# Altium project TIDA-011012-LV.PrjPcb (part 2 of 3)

## Sheet TIDA-011012-LV Communication.SchDoc
size 431 x 279 mm; Date: Not shown in title block; ApprovedBy: Not shown in title block; CheckedBy: Not shown in title block; Author: Not shown in title block; CompanyName: Not shown in title block; Engineer: Not shown in title block; Organization: Not shown in title block; Address1: Not shown in title block; Address2: Not shown in title block; Address3: Not shown in title block; Address4: Not shown in title block; DocumentNumber: 10; Revision: Use project parameter SCH_Rev; SheetNumber: 10; SheetTotal: 10; PageSetup: Record=PageOptions¦CenterHorizontal=True¦CenterVertical=True¦PrintScale=1.00¦XCorrection=1.00¦YCorrection=1.00¦PrintKind=0¦BorderSize=5000000¦LeftOffset=0¦BottomOffset=0¦Orientation=2¦PaperLength=1000¦PaperWidth=1000¦Scale=100¦PaperSource=15¦PrintQuality=600¦MediaType=1¦DitherType=10¦PaperKind=Letter¦PrintScaleMode=1
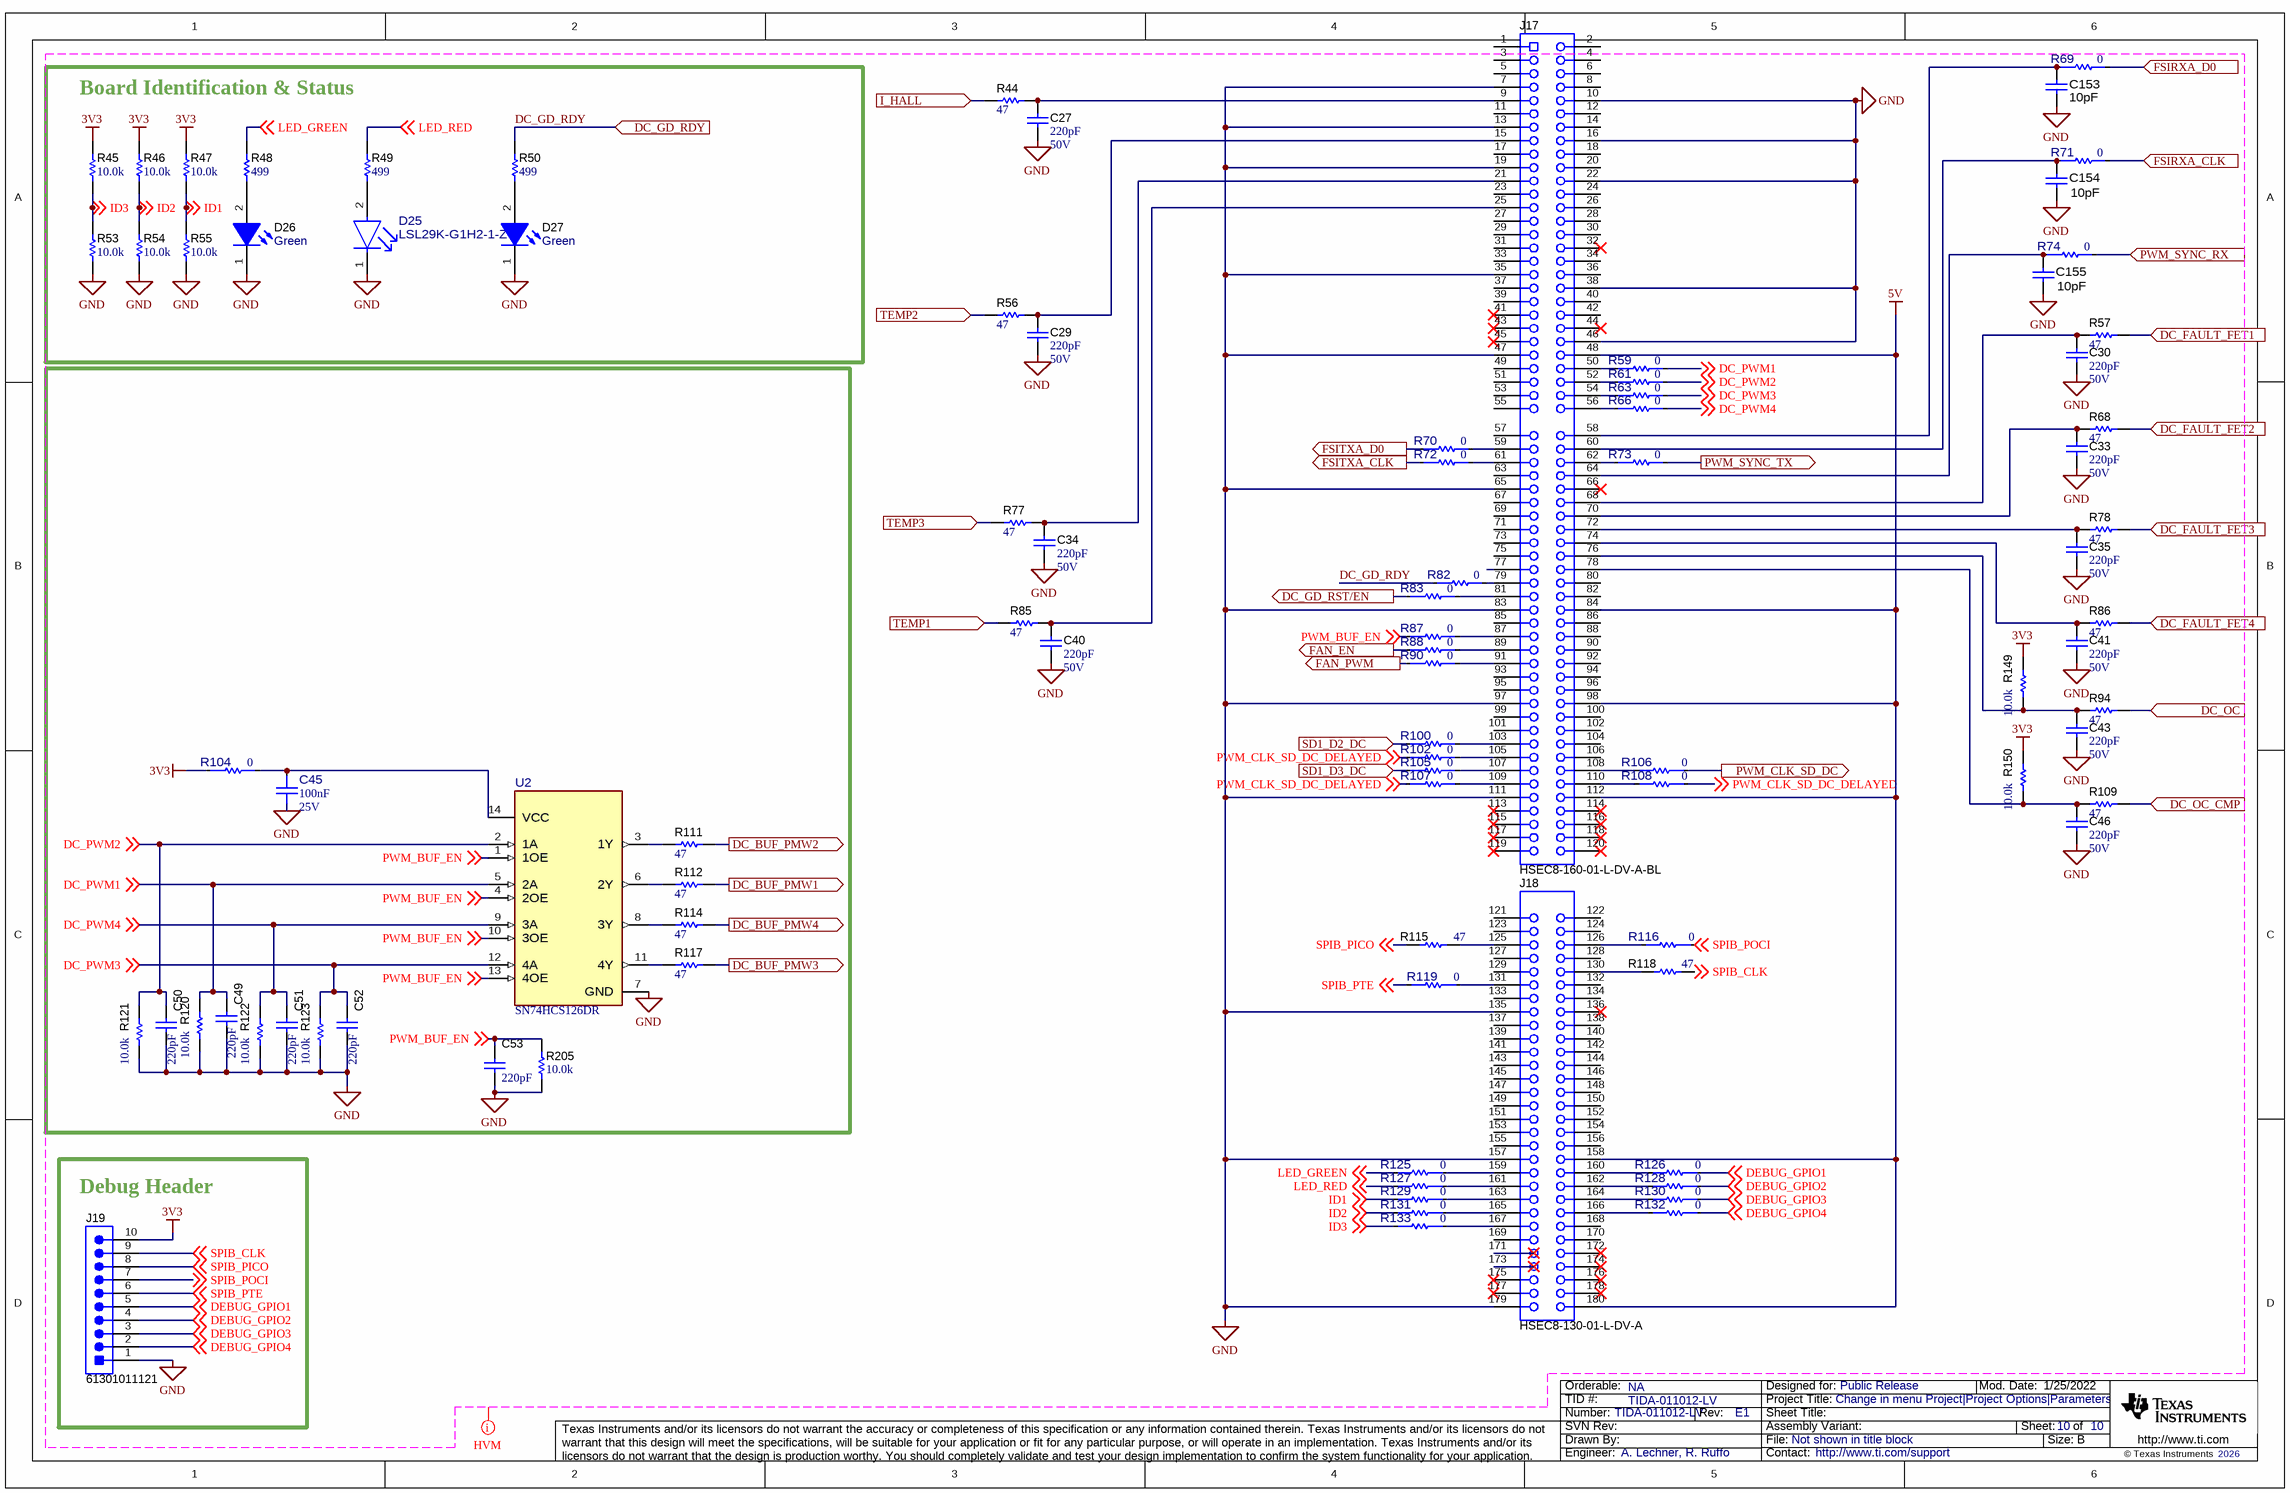
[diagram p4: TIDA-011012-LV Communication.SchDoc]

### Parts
C27  Cap_F: 220pF  VDC_V: 50V  [0603]  (hidden comment: C0603X221K5RACTU)
C29  Cap_F: 220pF  VDC_V: 50V  [0603]  (hidden comment: C0603X221K5RACTU)
C30  Cap_F: 220pF  VDC_V: 50V  [0603]  (hidden comment: C0603X221K5RACTU)
C33  Cap_F: 220pF  VDC_V: 50V  [0603]  (hidden comment: C0603X221K5RACTU)
C34  Cap_F: 220pF  VDC_V: 50V  [0603]  (hidden comment: C0603X221K5RACTU)
C35  Cap_F: 220pF  VDC_V: 50V  [0603]  (hidden comment: C0603X221K5RACTU)
C40  Cap_F: 220pF  VDC_V: 50V  [0603]  (hidden comment: C0603X221K5RACTU)
C41  Cap_F: 220pF  VDC_V: 50V  [0603]  (hidden comment: C0603X221K5RACTU)
C43  Cap_F: 220pF  VDC_V: 50V  [0603]  (hidden comment: C0603X221K5RACTU)
C45  Cap_F: 100nF  VDC_V: 25V  [FP-GMC10X7R104K25NT_0603-MFG]  (hidden comment: GMC10X7R104K25NT)
C46  Cap_F: 220pF  VDC_V: 50V  [0603]  (hidden comment: C0603X221K5RACTU)
C49  Cap_F: 220pF  [0603]  (hidden comment: C0603X221K5RACTU)
C50  Cap_F: 220pF  [0603]  (hidden comment: C0603X221K5RACTU)
C51  Cap_F: 220pF  [0603]  (hidden comment: C0603X221K5RACTU)
C52  Cap_F: 220pF  [0603]  (hidden comment: C0603X221K5RACTU)
C53  Cap_F: 220pF  [0603]  (hidden comment: C0603X221K5RACTU)
C153  Cap_F: 10pF  [0603]  (hidden comment: 0603ZC100KAT2A)
C154  Cap_F: 10pF  [0603]  (hidden comment: 0603ZC100KAT2A)
C155  Cap_F: 10pF  [0603]  (hidden comment: 0603ZC100KAT2A)
D25  LSL29K-G1H2-1-Z  [FP-LSL29K-G1H2-1-Z_0603-0]
D26  value Green  [WL-SMCW_GREEN]  (hidden comment: 150060VS75000)
D27  value Green  [WL-SMCW_GREEN]  (hidden comment: 150060VS75000)
J17  HSEC8-160-01-L-DV-A-BL  [controlCARD-120HSEC]
J18  HSEC8-130-01-L-DV-A  [controlCARD-180HSEC-60pinAddon]
J19  61301011121  [Wurth_61301011121]
R44  ValueDisplayed: 47  [0603]  (hidden comment: ERJ-3GEYJ470V)
R45  ValueDisplayed: 10.0k  [0603]  (hidden comment: ERJ-3EKF1002V)
R46  ValueDisplayed: 10.0k  [0603]  (hidden comment: ERJ-3EKF1002V)
R47  ValueDisplayed: 10.0k  [0603]  (hidden comment: ERJ-3EKF1002V)
R48  ValueDisplayed: 499  [0603]  (hidden comment: CRCW0603499RFKEAC)
R49  ValueDisplayed: 499  [0603]  (hidden comment: CRCW0603499RFKEAC)
R50  ValueDisplayed: 499  [0603]  (hidden comment: CRCW0603499RFKEAC)
R53  ValueDisplayed: 10.0k  [0603]  (hidden comment: ERJ-3EKF1002V)
R54  ValueDisplayed: 10.0k  [0603]  (hidden comment: ERJ-3EKF1002V)
R55  ValueDisplayed: 10.0k  [0603]  (hidden comment: ERJ-3EKF1002V)
R56  ValueDisplayed: 47  [0603]  (hidden comment: ERJ-3GEYJ470V)
R57  ValueDisplayed: 47  [0603]  (hidden comment: ERJ-3GEYJ470V)
R59  value 0  [FP-ERJ-H3G0R00V_0603-MFG]  (hidden comment: ERJ-H3G0R00V)
R61  value 0  [FP-ERJ-H3G0R00V_0603-MFG]  (hidden comment: ERJ-H3G0R00V)
R63  value 0  [FP-ERJ-H3G0R00V_0603-MFG]  (hidden comment: ERJ-H3G0R00V)
R66  value 0  [FP-ERJ-H3G0R00V_0603-MFG]  (hidden comment: ERJ-H3G0R00V)
R68  ValueDisplayed: 47  [0603]  (hidden comment: ERJ-3GEYJ470V)
R69  value 0  [FP-ERJ-H3G0R00V_0603-MFG]  (hidden comment: ERJ-H3G0R00V)
R70  value 0  [FP-ERJ-H3G0R00V_0603-MFG]  (hidden comment: ERJ-H3G0R00V)
R71  value 0  [FP-ERJ-H3G0R00V_0603-MFG]  (hidden comment: ERJ-H3G0R00V)
R72  value 0  [FP-ERJ-H3G0R00V_0603-MFG]  (hidden comment: ERJ-H3G0R00V)
R73  value 0  [FP-ERJ-H3G0R00V_0603-MFG]  (hidden comment: ERJ-H3G0R00V)
R74  value 0  [FP-ERJ-H3G0R00V_0603-MFG]  (hidden comment: ERJ-H3G0R00V)
R77  ValueDisplayed: 47  [0603]  (hidden comment: ERJ-3GEYJ470V)
R78  ValueDisplayed: 47  [0603]  (hidden comment: ERJ-3GEYJ470V)
R82  value 0  [FP-ERJ-H3G0R00V_0603-MFG]  (hidden comment: ERJ-H3G0R00V)
R83  value 0  [FP-ERJ-H3G0R00V_0603-MFG]  (hidden comment: ERJ-H3G0R00V)
R85  ValueDisplayed: 47  [0603]  (hidden comment: ERJ-3GEYJ470V)
R86  ValueDisplayed: 47  [0603]  (hidden comment: ERJ-3GEYJ470V)
R87  value 0  [FP-ERJ-H3G0R00V_0603-MFG]  (hidden comment: ERJ-H3G0R00V)
R88  value 0  [FP-ERJ-H3G0R00V_0603-MFG]  (hidden comment: ERJ-H3G0R00V)
R90  value 0  [FP-ERJ-H3G0R00V_0603-MFG]  (hidden comment: ERJ-H3G0R00V)
R94  ValueDisplayed: 47  [0603]  (hidden comment: ERJ-3GEYJ470V)
R100  value 0  [FP-ERJ-H3G0R00V_0603-MFG]  (hidden comment: ERJ-H3G0R00V)
R102  value 0  [FP-ERJ-H3G0R00V_0603-MFG]  (hidden comment: ERJ-H3G0R00V)
R104  value 0  [FP-ERJ-H3G0R00V_0603-MFG]  (hidden comment: ERJ-H3G0R00V)
R105  value 0  [FP-ERJ-H3G0R00V_0603-MFG]  (hidden comment: ERJ-H3G0R00V)
R106  value 0  [FP-ERJ-H3G0R00V_0603-MFG]  (hidden comment: ERJ-H3G0R00V)
R107  value 0  [FP-ERJ-H3G0R00V_0603-MFG]  (hidden comment: ERJ-H3G0R00V)
R108  value 0  [FP-ERJ-H3G0R00V_0603-MFG]  (hidden comment: ERJ-H3G0R00V)
R109  ValueDisplayed: 47  [0603]  (hidden comment: ERJ-3GEYJ470V)
R111  ValueDisplayed: 47  [0603]  (hidden comment: ERJ-3GEYJ470V)
R112  ValueDisplayed: 47  [0603]  (hidden comment: ERJ-3GEYJ470V)
R114  ValueDisplayed: 47  [0603]  (hidden comment: ERJ-3GEYJ470V)
R115  ValueDisplayed: 47  [0603]  (hidden comment: ERJ-3GEYJ470V)
R116  value 0  [FP-ERJ-H3G0R00V_0603-MFG]  (hidden comment: ERJ-H3G0R00V)
R117  ValueDisplayed: 47  [0603]  (hidden comment: ERJ-3GEYJ470V)
R118  ValueDisplayed: 47  [0603]  (hidden comment: ERJ-3GEYJ470V)
R119  value 0  [FP-ERJ-H3G0R00V_0603-IPC_B]  (hidden comment: ERJ-H3G0R00V)
R120  ValueDisplayed: 10.0k  [0603]  (hidden comment: ERJ-3EKF1002V)
R121  ValueDisplayed: 10.0k  [0603]  (hidden comment: ERJ-3EKF1002V)
R122  ValueDisplayed: 10.0k  [0603]  (hidden comment: ERJ-3EKF1002V)
R123  ValueDisplayed: 10.0k  [0603]  (hidden comment: ERJ-3EKF1002V)
R125  value 0  [FP-ERJ-H3G0R00V_0603-MFG]  (hidden comment: ERJ-H3G0R00V)
R126  value 0  [FP-ERJ-H3G0R00V_0603-MFG]  (hidden comment: ERJ-H3G0R00V)
R127  value 0  [FP-ERJ-H3G0R00V_0603-MFG]  (hidden comment: ERJ-H3G0R00V)
R128  value 0  [FP-ERJ-H3G0R00V_0603-MFG]  (hidden comment: ERJ-H3G0R00V)
R129  value 0  [FP-ERJ-H3G0R00V_0603-MFG]  (hidden comment: ERJ-H3G0R00V)
R130  value 0  [FP-ERJ-H3G0R00V_0603-MFG]  (hidden comment: ERJ-H3G0R00V)
R131  value 0  [FP-ERJ-H3G0R00V_0603-MFG]  (hidden comment: ERJ-H3G0R00V)
R132  value 0  [FP-ERJ-H3G0R00V_0603-MFG]  (hidden comment: ERJ-H3G0R00V)
R133  value 0  [FP-ERJ-H3G0R00V_0603-MFG]  (hidden comment: ERJ-H3G0R00V)
R149  ValueDisplayed: 10.0k  [0603]  (hidden comment: ERJ-3EKF1002V)
R150  ValueDisplayed: 10.0k  [0603]  (hidden comment: ERJ-3EKF1002V)
R205  ValueDisplayed: 10.0k  [0603]  (hidden comment: ERJ-3EKF1002V)
U2  SN74HCS126DR  [D0014A-MFG]

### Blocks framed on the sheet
Board Identification & Status: D25-D27 R45-R50 R53-R55
Debug Header: J19

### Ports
DC_BUF_PMW1 (out), DC_BUF_PMW2 (out), DC_BUF_PMW3 (out), DC_BUF_PMW4 (out), DC_FAULT_FET1 (in), DC_FAULT_FET2 (in), DC_FAULT_FET3 (in), DC_FAULT_FET4 (in), DC_GD_RDY (in), DC_GD_RST/EN (out), DC_OC (in), DC_OC_CMP (in), FAN_EN (out), FAN_PWM (out), FSIRXA_CLK (in), FSIRXA_D0 (in), FSITXA_CLK (out), FSITXA_D0 (out), I_HALL (in), PWM_CLK_SD_DC (out), PWM_SYNC_RX (in), PWM_SYNC_TX (out), SD1_D2_DC (in), SD1_D3_DC (in), TEMP1 (in), TEMP2 (in), TEMP3 (in)

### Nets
3V3: J19.10 R45.2 R46.2 R47.2 R104.1 R149.2 R150.2
5V: J17.48 J17.84 J17.98 J17.112 J18.158 J18.180
GND: C27.2 C29.2 C30.2 C33.2 C34.2 C35.2 C40.2 C41.2 C43.2 C45.1 C46.2 C49.1 C50.1 C51.1 C52.1 C53.1 C153.2 C154.2 C155.2 D25.1(CATHODE) D26.1(K) D27.1(K) J17.7 J17.10 J17.13 J17.16 J17.19 J17.22 J17.35 J17.38 J17.46 J17.47 J17.65 J17.83 J17.97 J17.111 J18.135 J18.157 J18.179 J19.1 R53.1 R54.1 R55.1 R120.1 R121.1 R122.1 R123.1 R205.1 U2.7(GND)
CLK_MOD_DC: R106.1 ; port PWM_CLK_SD_DC
DATA_I_DC: R100.1 ; port SD1_D2_DC
DATA_V_DC: R105.1 ; port SD1_D3_DC
DC_BUF_PMW1: R112.2 ; port DC_BUF_PMW1
DC_BUF_PMW2: R111.2 ; port DC_BUF_PMW2
DC_BUF_PMW3: R117.2 ; port DC_BUF_PMW3
DC_BUF_PMW4: R114.2 ; port DC_BUF_PMW4
DC_FAULT_FET1: R57.2 ; port DC_FAULT_FET1
DC_FAULT_FET2: R68.2 ; port DC_FAULT_FET2
DC_FAULT_FET3: R78.2 ; port DC_FAULT_FET3
DC_FAULT_FET4: R86.2 ; port DC_FAULT_FET4
DC_GD_RDY: R50.2 R82.1 ; port DC_GD_RDY
DC_GD_RST/EN: R83.1 ; port DC_GD_RST/EN
DC_OC: R94.2 ; port DC_OC
DC_OC_CMP: R109.2 ; port DC_OC_CMP
DC_PWM1: C49.2 R59.2 R120.2 U2.5(2A) ; off-sheet DC_PWM1
DC_PWM2: C50.2 R61.2 R121.2 U2.2(1A) ; off-sheet DC_PWM2
DC_PWM3: C52.2 R63.2 R123.2 U2.12(4A) ; off-sheet DC_PWM3
DC_PWM4: C51.2 R66.2 R122.2 U2.9(3A) ; off-sheet DC_PWM4
DEBUG_GPIO1: J19.5 R126.1 ; off-sheet DEBUG_GPIO1
DEBUG_GPIO2: J19.4 R128.1 ; off-sheet DEBUG_GPIO2
DEBUG_GPIO3: J19.3 R130.1 ; off-sheet DEBUG_GPIO3
DEBUG_GPIO4: J19.2 R132.1 ; off-sheet DEBUG_GPIO4
FAN_EN: R88.1 ; port FAN_EN
FAN_PWM: R90.1 ; port FAN_PWM
FSIRXA_CLK: R71.2 ; port FSIRXA_CLK
FSIRXA_D0: R69.2 ; port FSIRXA_D0
FSITXA_CLK: R72.1 ; port FSITXA_CLK
FSITXA_D0: R70.1 ; port FSITXA_D0
I_HALL: R44.1 ; port I_HALL
ID1: R47.1 R55.2 R129.2 ; off-sheet ID1
ID2: R46.1 R54.2 R131.2 ; off-sheet ID2
ID3: R45.1 R53.2 R133.2 ; off-sheet ID3
LED_GREEN: R48.2 R125.2 ; off-sheet LED_GREEN
LED_RED: R49.2 R127.2 ; off-sheet LED_RED
PWM_BUF_EN: C53.2 R87.1 R205.2 U2.1(1OE) U2.4(2OE) U2.10(3OE) U2.13(4OE) ; off-sheet PWM_BUF_EN
PWM_CLK_SD_DC_DELAYED: R102.1 R107.1 R108.1 ; off-sheet PWM_CLK_SD_DC_DELAYED
PWM_SYNC_RX: R74.2 ; port PWM_SYNC_RX
PWM_SYNC_TX: R73.2 ; port PWM_SYNC_TX
SPIB_CLK: J19.9 R118.2 ; off-sheet SPIB_CLK
SPIB_PICO: J19.8 R115.1 ; off-sheet SPIB_PICO
SPIB_POCI: J19.7 R116.1 ; off-sheet SPIB_POCI
SPIB_PTE: J19.6 R119.2 ; off-sheet SPIB_PTE
TEMP1: R85.1 ; port TEMP1
TEMP2: R56.1 ; port TEMP2
TEMP3: R77.1 ; port TEMP3
NetC27_1: C27.1 J17.9 R44.2
NetC29_1: C29.1 J17.15 R56.2
NetC30_1: C30.1 J17.68 R57.1
NetC33_1: C33.1 J17.70 R68.1
NetC34_1: C34.1 J17.21 R77.2
NetC35_1: C35.1 J17.72 R78.1
NetC40_1: C40.1 J17.25 R85.2
NetC41_1: C41.1 J17.74 R86.1
NetC43_1: C43.1 J17.76 R94.1 R149.1
NetC45_2: C45.2 R104.2 U2.14(VCC)
NetC46_1: C46.1 J17.78 R109.1 R150.1
NetC153_1: C153.1 J17.58 R69.1
NetC154_1: C154.1 J17.60 R71.1
NetC155_1: C155.1 J17.64 R74.1
NetD25_2: D25.2(ANODE) R49.1
NetD26_2: D26.2(A) R48.1
NetD27_2: D27.2(A) R50.1
NetJ17_50: J17.50 R59.1
NetJ17_52: J17.52 R61.1
NetJ17_54: J17.54 R63.1
NetJ17_56: J17.56 R66.1
NetJ17_59: J17.59 R70.2
NetJ17_61: J17.61 R72.2
NetJ17_62: J17.62 R73.1
NetJ17_79: J17.79 R82.2
NetJ17_81: J17.81 R83.2
NetJ17_87: J17.87 R87.2
NetJ17_89: J17.89 R88.2
NetJ17_91: J17.91 R90.2
NetJ17_103: J17.103 R100.2
NetJ17_105: J17.105 R102.2
NetJ17_107: J17.107 R105.2
NetJ17_108: J17.108 R106.2
NetJ17_109: J17.109 R107.2
NetJ17_110: J17.110 R108.2
NetJ18_125: J18.125 R115.2
NetJ18_126: J18.126 R116.2
NetJ18_130: J18.130 R118.1
NetJ18_131: J18.131 R119.1
NetJ18_159: J18.159 R125.1
NetJ18_160: J18.160 R126.2
NetJ18_161: J18.161 R127.1
NetJ18_162: J18.162 R128.2
NetJ18_163: J18.163 R129.1
NetJ18_164: J18.164 R130.2
NetJ18_165: J18.165 R131.1
NetJ18_166: J18.166 R132.2
NetJ18_167: J18.167 R133.1
NetR111_1: R111.1 U2.3(1Y)
NetR112_1: R112.1 U2.6(2Y)
NetR114_1: R114.1 U2.8(3Y)
NetR117_1: R117.1 U2.11(4Y)

Not connected (* = marked no-connect by the designer): J17 1 2 3 4 5 6 8 11 12 14 17 18 20 23 24 26 27 28 29 30 31 32* 33 34 36 37 39 40 41* 42 43* 44* 45* 49 51 53 55 57 63 66* 67 69 71 73 75 77 80 82 85 86 88 90 92 93 94 95 96 99 100 101 102 104 106 113* 114* 115* 116* 117* 118* 119* 120*; J18 121 122 123 124 127 128 129 132 133 134 136* 137 138 139 140 141 142 143 144 145 146 147 148 149 150 151 152 153 154 155 156 168 169 170 171* 172* 173* 174* 175* 176* 177* 178*

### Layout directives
net class HVM: 3V3, 5V, DC_GD_RDY, DC_PWM1, DC_PWM2, DC_PWM3, DC_PWM4, DEBUG_GPIO1, DEBUG_GPIO2, DEBUG_GPIO3, DEBUG_GPIO4, GND, ID1, ID2, ID3, LED_GREEN, LED_RED, PWM_BUF_EN, PWM_CLK_SD_DC_DELAYED, SPIB_CLK, SPIB_PICO, SPIB_POCI, SPIB_PTE

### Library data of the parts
C27 C29 C30 C33-C35 C40 C41 C43 C46 = CMP-0006982-4: CAP, CERM, 220 pF, 50 V, +/- 10%, X7R, 0603; Manufacturer: Kemet; TaMin_C: -55°C; Polarized: N; SizeAreaWB_mm2: 4.68; Value1: Unknown; U/M: EA; Value: 220pF; TaMax_C: 125°C; SizeZ_mm: 1; SizeX_mm: 1.6; SizeY_mm: 0.8; SizeArea_mm2: 1.28; AEC Category: Q200
C45 = CMP-0094950-1: 0.1 µF ±10% 25V Ceramic Capacitor X7R 0603 (1608 Metric); Manufacturer: CAL-CHIP ELECTRONICS; AEC Qualified: No; SizeZ_mm: 1mm; Value: 100nF; ValueDisplayed: 0.1uF; TempCo: 30ppm/°C
C49-C53 = CMP-0006982-4: CAP, CERM, 220 pF, 50 V, +/- 10%, X7R, 0603; Manufacturer: Kemet; TaMin_C: -55°C; Polarized: N; SizeAreaWB_mm2: 4.68; Value1: Unknown; U/M: EA; Value: 220pF; TaMax_C: 125°C; SizeZ_mm: 1; SizeX_mm: 1.6; SizeY_mm: 0.8; Value2: 50V; SizeArea_mm2: 1.28; AEC Category: Q200
C153-C155 = CMP-0006811-4: CAP, CERM, 10 pF, 10 V, +/- 10%, X7R, 0603; Manufacturer: AVX; TaMin_C: -55°C; Polarized: N; SizeAreaWB_mm2: 4.68; Value1: Unknown; U/M: EA; Value: 10pF; TaMax_C: 125°C; SizeZ_mm: 1; SizeX_mm: 1.6; SizeY_mm: 0.8; Value2: 10V; SizeArea_mm2: 1.28; AEC Category: Q200
D25 = CMP-0092845-1: LED Uni-Color Red 643nm 2-Pin Chip 0603(1608Metric) T/R; Manufacturer: OSRAM Opto Semiconductors; AEC Grade: Grade 2; LuminousFlux_PhiV: 8.1/16.1lm; Vf_V: 1.8V; Forward Current: 2mA; Led Orientation: Top View; SizeZ_mm: 0.67mm; AEC Qualified: Yes; Luminous Intensity: 1.8-2.24/3.55-4.5mcd; Vr_V: 12V; Angle: 160°; LambdaD: 630nm; Tjmax_C: 110°C
D26 D27 = CMP-0002894-2: LED, Green, SMD; Manufacturer: Wurth Elektronik; Type: AlInGaP; Value2: 2V; Io_A: 20mA; Value1: W
J17 = CMP-0003814-2: C2000 controlCARD-120HSEC connector, SMT; Manufacturer: Samtec; Note: The pin numbering does not match Samtec datasheet
J18 = CMP-0003859-2: C2000 controlCARD-180HSEC (60-pin addon) connector, SMT; Manufacturer: Samtec; Note: The pin numbering does not match Samtec datasheet
J19 = CMP-0054804-1: Header, 2.54mm, 10x1, Gold, TH; Manufacturer: Wurth Elektronik; CNHeader: TRUE; Shrouded: N; Gender: Male; Row_Count: 1; Pitch_mm: 2.54; CT: FALSE
R44 R56 R57 R68 R77 R78 R85 R86 R94 R109 R111 R112 R114 R115 R117 R118 = CMP-0025880-3: RES, 47, 5%, 0.1 W, AEC-Q200 Grade 0, 0603; Manufacturer: Panasonic; Power_W: 100mW; TempCo: 200 ppm/C; Value_Code: 47R0; U/M: EA; Value: 47; EIA_Code: E24; SizeX_mm: 1.6; SizeY_mm: 0.8; SizeZ_mm: 1; Value2: 0.1W; SizeArea_mm2: 1.28; AEC Qualified: Y; AEC Grade: 0; AEC Category: Q200
R45-R47 R53-R55 R120-R123 R149 R150 R205 = CMP-0022684-3: RES, 10.0 k, 1%, 0.1 W, 0603; Manufacturer: Panasonic; Power_W: 100mW; TempCo: 100 ppm/C; Value_Code: 10k0; U/M: EA; Value: 10.0k; EIA_Code: E96; Res_ohm: 10k; SizeX_mm: 1.6; SizeY_mm: 0.8; SizeZ_mm: 1; Value2: 0.1W; SizeArea_mm2: 1.28; VDC_V: 75V; AEC Category: Q200
R48-R50 = CMP-0082532-1: RES, 499, 1%, 0.1 W, 0603; Manufacturer: Vishay-Dale; Power_W: 100mW; TempCo: 100 ppm/C; SizeAreaWB_mm2: 4.68; Value_Code: 499R; Value: 499; EIA_Code: E96; SizeX_mm: 1.6; SizeY_mm: 0.8; SizeZ_mm: 1; Value2: 0.1W; SizeArea_mm2: 1.28; AEC Qualified: N; VDC_V: 75V; AEC Category: Q200
R59 R61 R63 R66 R69-R74 R82 R83 R87 R88 R90 R100 R102 R104-R108 R116 R119 R125-R133 = CMP-0097467-1: 0 Ohms Jumper 0.125W, 1/8W Chip Resistor 0603 (1608 Metric) Automotive AEC-Q200 Thick Film; Manufacturer: Panasonic; VDC_V: 75V; Power_W: 125mW; AEC Qualified: Yes; SizeZ_mm: 0.55mm; AEC Grade: Grade 0
U2 = CMP-0093039-1: Schmitt-trigger inputs quadruple bus buffer gates with 3-state outputs 14-SOIC -40 to 125; Manufacturer: Texas Instruments; Min Supply Voltage: 2V; TJmax_C: +150°C; Logic Function Desc: Non-Inverting; Number Of Inputs: 1; AEC Qualified: No; Max Supply Voltage: 6V; SizeZ_mm: 1.75mm; PositionCount: 4; TaMin_C: -40°C; Standoff Height: 0.1mm; Nominal Supply Current: 0.1uA; TaMax_C: +125°C; Propagation Delay: 7ns

## Sheet TIDA-011012-LV DC IV Sensing.SchDoc
size 431 x 279 mm; Date: Not shown in title block; ApprovedBy: Not shown in title block; CheckedBy: Not shown in title block; Author: Not shown in title block; CompanyName: Not shown in title block; Engineer: Not shown in title block; Organization: Not shown in title block; Address1: Not shown in title block; Address2: Not shown in title block; Address3: Not shown in title block; Address4: Not shown in title block; DocumentNumber: 5; Revision: Use project parameter SCH_Rev; SheetNumber: 5; SheetTotal: 10; PageSetup: Record=PageOptions¦CenterHorizontal=True¦CenterVertical=True¦PrintScale=1.00¦XCorrection=1.00¦YCorrection=1.00¦PrintKind=0¦BorderSize=5000000¦LeftOffset=0¦BottomOffset=0¦Orientation=2¦PaperLength=1000¦PaperWidth=1000¦Scale=100¦PaperSource=15¦PrintQuality=600¦MediaType=1¦DitherType=10¦PaperKind=Letter¦PrintScaleMode=1
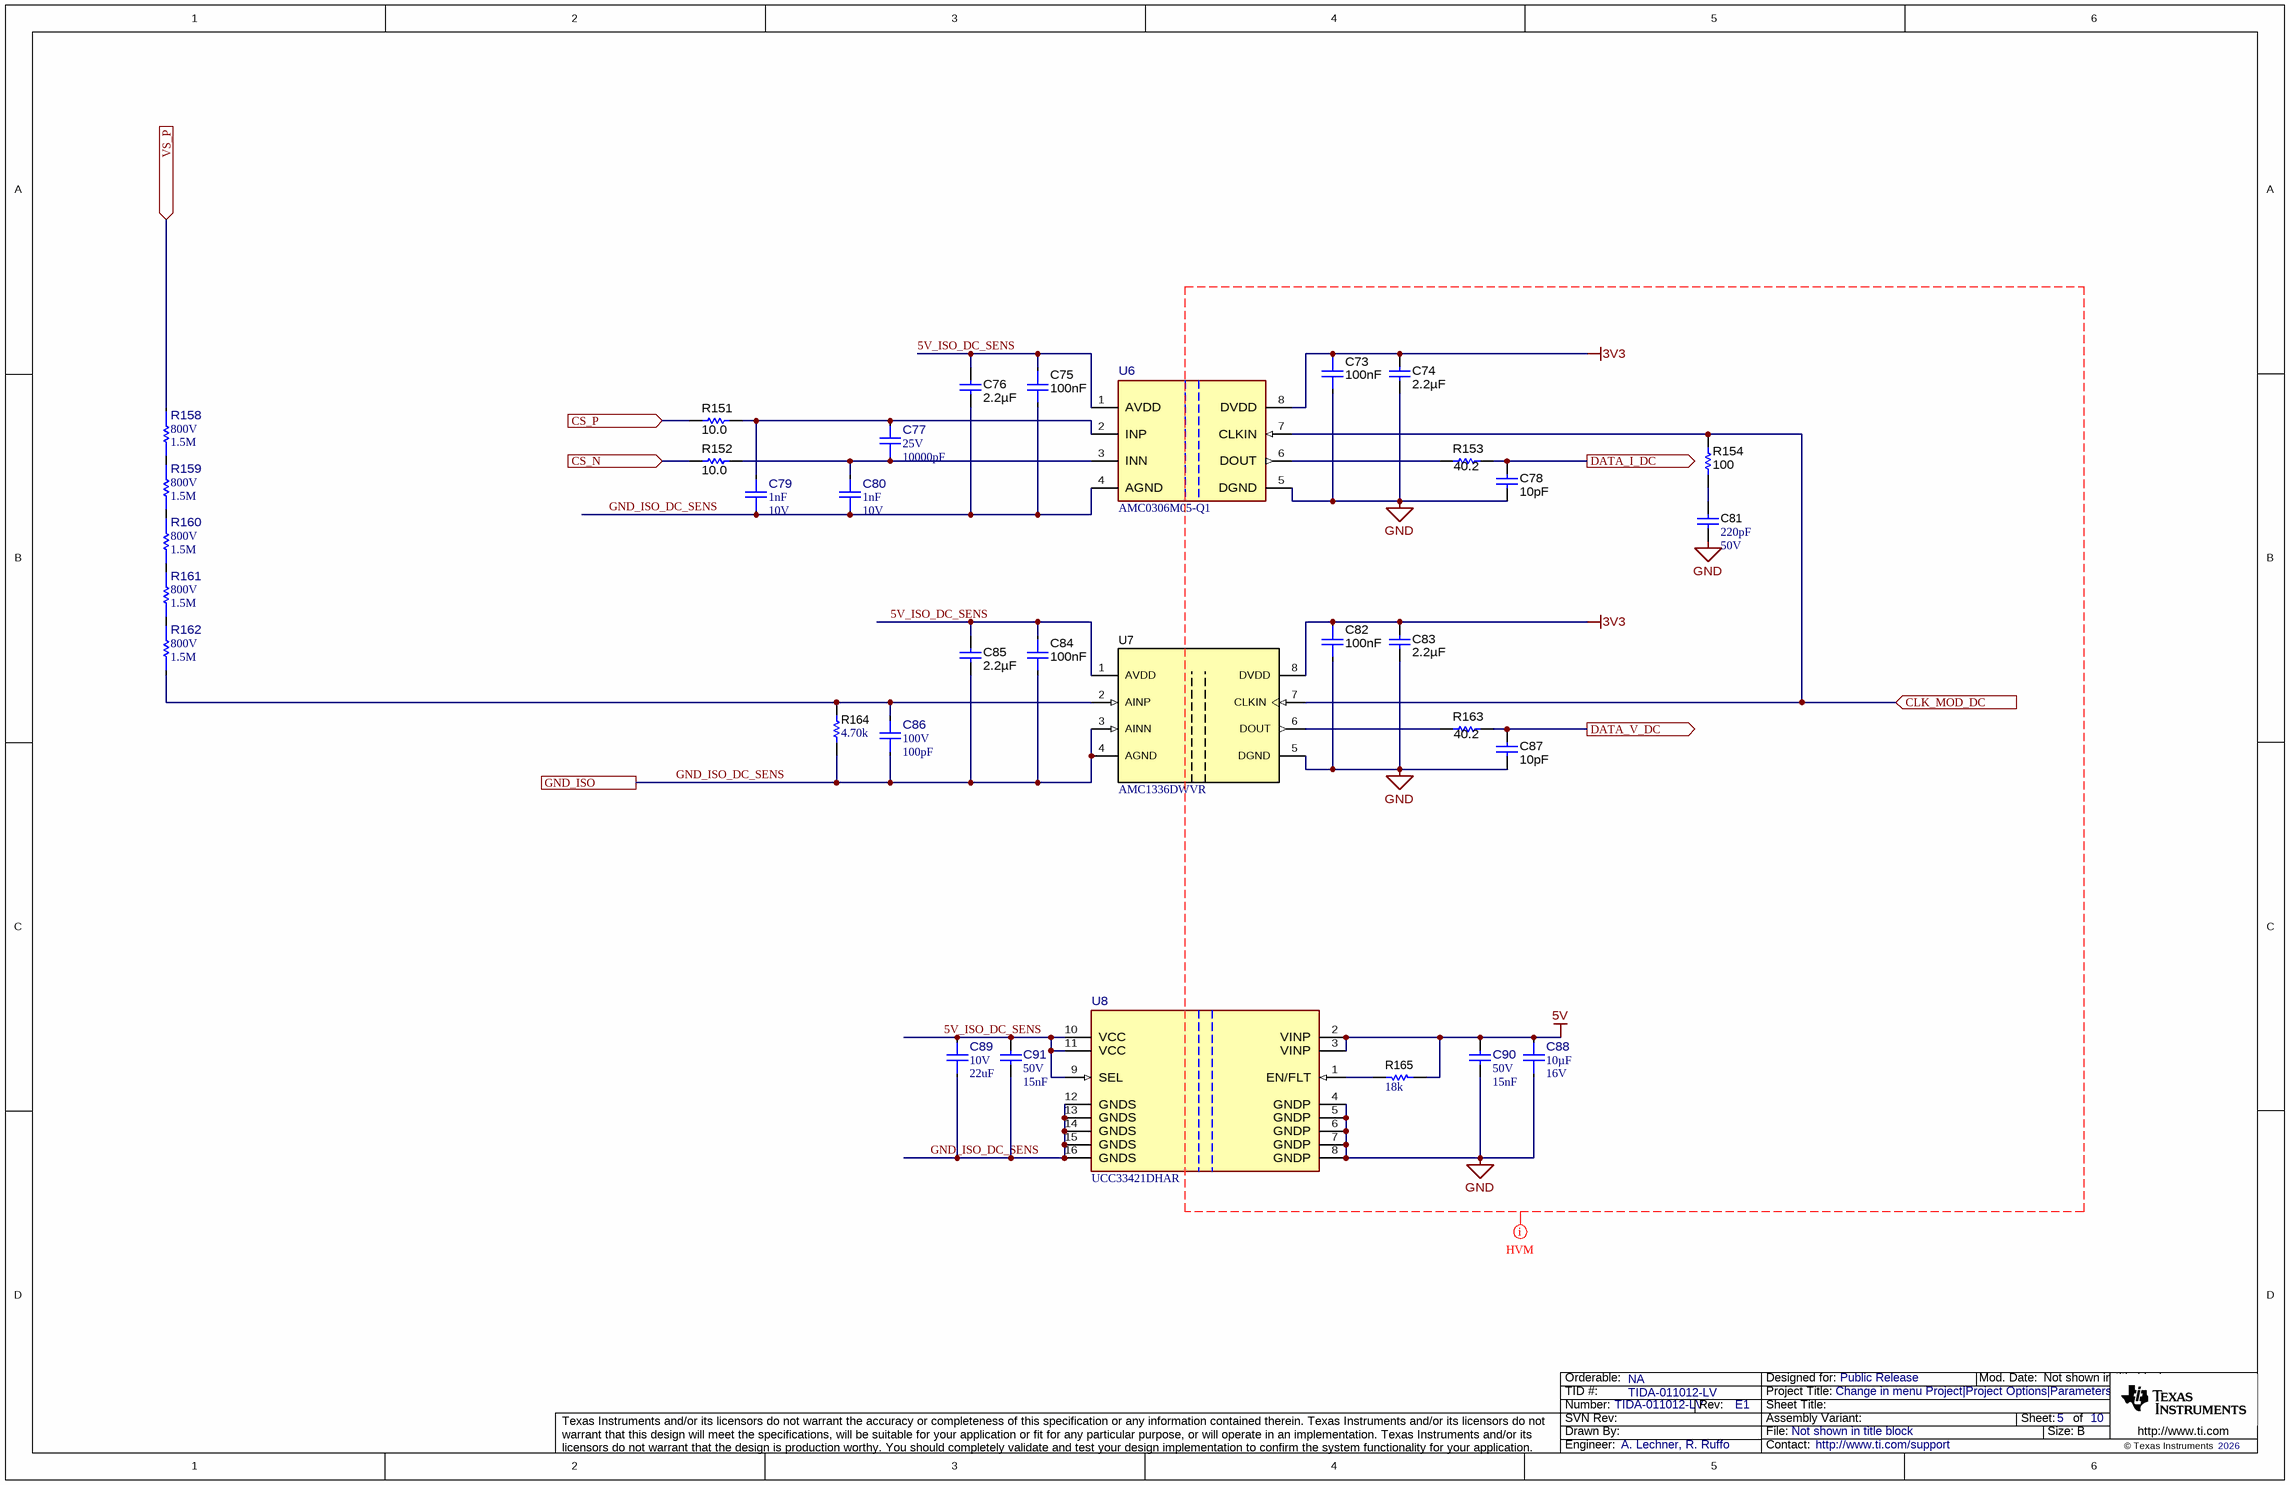
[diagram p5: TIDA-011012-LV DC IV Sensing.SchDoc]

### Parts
C73  Cap_F: 100nF  [FP-CL10B104KA8VPJC_0603-MFG]  (hidden comment: CL10B104KA8VPJC)
C74  Cap_F: 2.2µF  [0603]  (hidden comment: CC0603KRX7R7BB225)
C75  Cap_F: 100nF  [FP-CL10B104KA8VPJC_0603-MFG]  (hidden comment: CL10B104KA8VPJC)
C76  Cap_F: 2.2µF  [0603]  (hidden comment: CC0603KRX7R7BB225)
C77  VDC_V: 25V  ValueDisplayed: 10000pF  [FP-C0603C103J3GAC7867_0603-MFG]  (hidden comment: C0603C103J3GAC7867)
C78  Cap_F: 10pF  [0603]  (hidden comment: 0603ZC100KAT2A)
C79  Cap_F: 1nF  VDC_V: 10V  [FP-0603ZC102KAT2A_0603-MFG]  (hidden comment: 0603ZC102KAT2A)
C80  Cap_F: 1nF  VDC_V: 10V  [FP-0603ZC102KAT2A_0603-MFG]  (hidden comment: 0603ZC102KAT2A)
C81  Cap_F: 220pF  VDC_V: 50V  [0603]  (hidden comment: C0603X221K5RACTU)
C82  Cap_F: 100nF  [FP-CL10B104KA8VPJC_0603-MFG]  (hidden comment: CL10B104KA8VPJC)
C83  Cap_F: 2.2µF  [0603]  (hidden comment: CC0603KRX7R7BB225)
C84  Cap_F: 100nF  [FP-CL10B104KA8VPJC_0603-MFG]  (hidden comment: CL10B104KA8VPJC)
C85  Cap_F: 2.2µF  [0603]  (hidden comment: CC0603KRX7R7BB225)
C86  VDC_V: 100V  Cap_F: 100pF  [FP-06031C101JAT2A_0603-MFG]  (hidden comment: 06031C101JAT2A)
C87  Cap_F: 10pF  [0603]  (hidden comment: 0603ZC100KAT2A)
C88  Cap_F: 10µF  VDC_V: 16V  [FP-MA0805XR106K160_0805-IPC_C]  (hidden comment: MA0805XR106K160)
C89  VDC_V: 10V  ValueDisplayed: 22uF  [FP-GRT21BD71A226ME13L_0805-MFG]  (hidden comment: GRT21BD71A226ME13L)
C90  VDC_V: 50V  Cap_F: 15nF  [FP-C0603C153K5RACTU_0603-IPC_A]  (hidden comment: C0603C153K5RACTU)
C91  VDC_V: 50V  Cap_F: 15nF  [FP-C0603C153K5RACTU_0603-IPC_A]  (hidden comment: C0603C153K5RACTU)
R151  ValueDisplayed: 10.0  [0603]  (hidden comment: TNPW060310R0BEEA)
R152  ValueDisplayed: 10.0  [0603]  (hidden comment: TNPW060310R0BEEA)
R153  ValueDisplayed: 40.2  [0603]  (hidden comment: RC0603FR-0740R2L)
R154  ValueDisplayed: 100  [0603]  (hidden comment: RC0603FR-07100RL)
R158  value 1.5M  VDC_V: 800V  [FP-CHV1206-FX-1504ELF_1206-MFG]  (hidden comment: CHV1206-FX-1504ELF)
R159  value 1.5M  VDC_V: 800V  [FP-CHV1206-FX-1504ELF_1206-MFG]  (hidden comment: CHV1206-FX-1504ELF)
R160  value 1.5M  VDC_V: 800V  [FP-CHV1206-FX-1504ELF_1206-MFG]  (hidden comment: CHV1206-FX-1504ELF)
R161  value 1.5M  VDC_V: 800V  [FP-CHV1206-FX-1504ELF_1206-MFG]  (hidden comment: CHV1206-FX-1504ELF)
R162  value 1.5M  VDC_V: 800V  [FP-CHV1206-FX-1504ELF_1206-MFG]  (hidden comment: CHV1206-FX-1504ELF)
R163  ValueDisplayed: 40.2  [0603]  (hidden comment: RC0603FR-0740R2L)
R164  ValueDisplayed: 4.70k  [0603]  (hidden comment: RC0603FR-074K7L)
R165  ValueDisplayed: 18k  [0603]  (hidden comment: RC0603JR-0718KL)
U6  AMC0306M05-Q1  [DWV0008A-MFG]
U7  AMC1336DWVR  [DWV0008A]
U8  UCC33421DHAR  [DHA0016A-MFG]

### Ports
CLK_MOD_DC (in), CS_N (in), CS_P (in), DATA_I_DC (out), DATA_V_DC (out), GND_ISO, VS_P (in)

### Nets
3V3: C73.1 C74.1 C82.1 C83.1 U6.8(DVDD) U7.8(DVDD)
5V: C88.2 C90.1 R165.2 U8.2(VINP) U8.3(VINP)
GND: C73.2 C74.2 C78.2 C81.2 C82.2 C83.2 C87.2 C88.1 C90.2 U6.5(DGND) U7.5(DGND) U8.4(GNDP) U8.5(GNDP) U8.6(GNDP) U8.7(GNDP) U8.8(GNDP)
5V_ISO_DC_SENS: C75.1 C76.1 C84.1 C85.1 C89.2 C91.1 U6.1(AVDD) U7.1(AVDD) U8.9(SEL) U8.10(VCC) U8.11(VCC)
CLK_MOD_DC: R154.2 U6.7(CLKIN) U7.7(CLKIN) ; port CLK_MOD_DC
DATA_I_DC: C78.1 R153.2 ; port DATA_I_DC
DATA_V_DC: C87.1 R163.2 ; port DATA_V_DC
DC_POS: R158.1 ; port VS_P
GND_ISO_DC_SENS: C75.2 C76.2 C79.1 C80.1 C84.2 C85.2 C86.1 C89.1 C91.2 R164.1 U6.4(AGND) U7.3(AINN) U7.4(AGND) U8.12(GNDS) U8.13(GNDS) U8.14(GNDS) U8.15(GNDS) U8.16(GNDS) ; port GND_ISO  [project net DC_DAB]
I_DC_MINUS: R152.1 ; port CS_N
I_DC_POS: R151.1 ; port CS_P
NetC77_1: C77.1 C80.2 R152.2 U6.3(INN)
NetC77_2: C77.2 C79.2 R151.2 U6.2(INP)
NetC81_1: C81.1 R154.1
NetC86_2: C86.2 R162.2 R164.2 U7.2(AINP)
NetR153_1: R153.1 U6.6(DOUT)
NetR158_2: R158.2 R159.1
NetR159_2: R159.2 R160.1
NetR160_2: R160.2 R161.1
NetR161_2: R161.2 R162.1
NetR163_1: R163.1 U7.6(DOUT)
NetR165_1: R165.1 U8.1(EN/FLT)

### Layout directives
net class HVM: 3V3, 5V, GND

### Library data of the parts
C73 C75 C82 C84 = CMP-0121051-1: Automotive CAP, 100㎋, 25V, ±10%, X7R, 0603, 5mm Bending; Manufacturer: Samsung; AEC Grade: Grade 1; AEC Qualified: Yes; SizeZ_mm: 0.9mm; TempCo: 15%; Value: 100nF
C74 C76 C83 C85 = CMP-0079605-1: CAP, CERM, 2.2 µF, 16 V,+/- 10%, X7R, 0603; Manufacturer: Yageo America; TaMin_C: -55°C; Polarized: N; SizeAreaWB_mm2: 4.68; U/M: EA; Value: 2.2uF; TaMax_C: 125°C; SizeZ_mm: 1; SizeX_mm: 1.6; SizeY_mm: 0.8; Value2: 16V; SizeArea_mm2: 1.28; AEC Category: Q200
C77 = CMP-0095473-1: 10000 pF ±5% 25V Ceramic Capacitor C0G, NP0 0603 (1608 Metric); Manufacturer: KEMET; Cap_F: 10nF; SizeZ_mm: 0.87mm; TempCo: 30ppm/°C; Value: 10nF; AEC Qualified: No
C78 C87 = CMP-0006811-4: as C153-C155 on sheet TIDA-011012-LV Communication
C79 C80 = CMP-0120686-1: 1000 pF ±10% 10V Ceramic Capacitor X7R 0603 (1608 Metric); Manufacturer: KYOCERA AVX; AEC Qualified: No; SizeZ_mm: 0.9mm; TempCo: 15%; Value: 1nF
C81 = CMP-0006982-4: as C27 on sheet TIDA-011012-LV Communication
C86 = CMP-0096605-1: 100 pF ±5% 100V Ceramic Capacitor X7R 0603 (1608 Metric); Manufacturer: KYOCERA AVX; TempCo: 15%; AEC Qualified: No; SizeZ_mm: 0.9mm; Value: 100pF
C88 = CMP-0121624-1: 10 µF ±10% 16V Ceramic Capacitor X7R 0805 (2012 Metric); Manufacturer: Meritek; AEC Qualified: No; SizeZ_mm: 1.45mm; TempCo: 15%; ValueDisplayed: 10uF; Value: 10µF
C89 = CMP-0095621-1: 22μF ±20% 10V Ceramic Capacitor X7T 0805 (2012 Metric); Manufacturer: Murata; AEC Qualified: Yes; SizeZ_mm: 1.45mm; TempCo: +22/-33%; AEC Grade: Grade 1
C90 C91 = CMP-0086419-2: Cap Ceramic 0.015uF 50V X7R 10% Pad SMD 0603 125°C T/R; Manufacturer: Kemet; SizeZ_mm: 0.87mm; AEC Qualified: No; TempCo: 15%; Symbol Name: SYM-C0603C153K5RACTU
R151 R152 = CMP-0025687-2: RES, 10.0, 0.1%, 0.1 W, 0603; Manufacturer: Vishay-Dale; Power_W: 100mW; TempCo: 25 ppm/C; Value_Code: 10R0; U/M: EA; Value: 10.0; EIA_Code: E192; Res_ohm: 10; SizeX_mm: 1.6; SizeY_mm: 0.8; SizeZ_mm: 1; Value2: 0.1W; SizeArea_mm2: 1.28; VDC_V: 75V; AEC Category: Q200
R153 R163 = CMP-0023099-5: RES, 40.2, 1%, 0.1 W, 0603; Manufacturer: Yageo; Power_W: 100mW; TempCo: 100 ppm/C; Value_Code: 40R2; Value: 40.2; EIA_Code: E96; SizeX_mm: 1.6; SizeY_mm: 0.8; SizeZ_mm: 1; Value2: 0.1W; SizeArea_mm2: 1.28; AEC Qualified: N; VDC_V: 75V; AEC Category: Q200; SizeAreaWB_mm2: 4.68
R154 = CMP-0022736-4: RES, 100, 1%, 0.1 W, 0603; Manufacturer: Yageo; Power_W: 100mW; TempCo: 100 ppm/C; Value_Code: 100R; Value: 100; EIA_Code: E96; SizeX_mm: 1.6; SizeY_mm: 0.8; SizeZ_mm: 1; Value2: 0.1W; SizeArea_mm2: 1.28; AEC Qualified: N; VDC_V: 75V; AEC Category: Q200; SizeAreaWB_mm2: 4.68
R158-R162 = CMP-0120473-1: Thick Film High Voltage Chip Resistors 1206 1.5MOhm ±1% ±100ppm/°C; Manufacturer: Bourns; AEC Qualified: No; Power_W: 250mW; SizeZ_mm: 0.65mm
R164 = CMP-0023153-5: RES, 4.70 k, 1%, 0.1 W, 0603; Manufacturer: Yageo; Power_W: 100mW; TempCo: 100 ppm/C; Value_Code: 4k70; Value: 4.70k; Res_ohm: 4.7k; SizeX_mm: 1.6; SizeY_mm: 0.8; SizeZ_mm: 1; Value2: 0.1W; SizeArea_mm2: 1.28; AEC Qualified: N; VDC_V: 75V; AEC Category: Q200; SizeAreaWB_mm2: 4.68
R165 = CMP-0025892-5: RES, 18 k, 5%, 0.1 W, 0603; Manufacturer: Yageo; Power_W: 100mW; TempCo: 100 ppm/C; Value_Code: 18k0; Value: 18k; EIA_Code: E24; SizeX_mm: 1.6; SizeY_mm: 0.8; SizeZ_mm: 1; Value2: 0.1W; SizeArea_mm2: 1.28; AEC Qualified: N; VDC_V: 75V; AEC Category: Q200; SizeAreaWB_mm2: 4.68
U6 = CMP-0125127-1: Automotive, Precision, ±250-mV Input Isolated Delta-Sigma Modulators With External Clock; Manufacturer: Texas Instruments; SizeZ_mm: 2.8mm; AEC Qualified: Yes; AEC Grade: Grade 1; Max Supply Voltage: 5.5V; Min Supply Voltage: 2.7V; Standoff Height: 0.36mm; TaMax_C: +125°C; TaMin_C: -40°C; TJmax_C: +150°C
U7 = CMP-0860008-1: AMC1336 Small, High-Precision, Reinforced Isolated Delta-Sigma Modulator With Input Optimized for Voltage Sensing Applications, DWV0008A (SOIC-8); Manufacturer: Texas Instruments; AEC Qualified: N; AEC Category: Q200; SizeY_mm: 5.85; SizeX_mm: 11.5; SizeAreaWB_mm2: 105.975; SizeArea_mm2: 67.275; CompType: IC; SizeZ_mm: 2.8
U8 = CMP-0123146-1: Ultra-Small, 1.5W, 5.0V, 5kVRMS Isolation, Industrial DC/DC Module; Manufacturer: Texas Instruments; SizeZ_mm: 2.6mm; AEC Qualified: No; Max Supply Voltage: 5.5V; Min Supply Voltage: 4.5V; Nominal Supply Current: 7-545mA; Number Of Outputs: 1; Output Type: AdjustableProgrammable; Output Voltage: 5/5.5V; Standoff Height: 0.1mm; Switching Frequency: 76MHz; Switching Topology: Boost; TaMax_C: +125°C; TaMin_C: -40°C; TJmax_C: +150°C

## Sheet TIDA-011012-LV Current Comparator.SchDoc
size 431 x 279 mm; Date: Not shown in title block; ApprovedBy: Not shown in title block; CheckedBy: Not shown in title block; Author: Not shown in title block; CompanyName: Not shown in title block; Engineer: Not shown in title block; Organization: Not shown in title block; Address1: Not shown in title block; Address2: Not shown in title block; Address3: Not shown in title block; Address4: Not shown in title block; DocumentNumber: 6; Revision: Use project parameter SCH_Rev; SheetNumber: 6; SheetTotal: 10; PageSetup: Record=PageOptions¦CenterHorizontal=True¦CenterVertical=True¦PrintScale=1.00¦XCorrection=1.00¦YCorrection=1.00¦PrintKind=0¦BorderSize=5000000¦LeftOffset=0¦BottomOffset=0¦Orientation=2¦PaperLength=1000¦PaperWidth=1000¦Scale=100¦PaperSource=15¦PrintQuality=600¦MediaType=1¦DitherType=10¦PaperKind=Letter¦PrintScaleMode=1
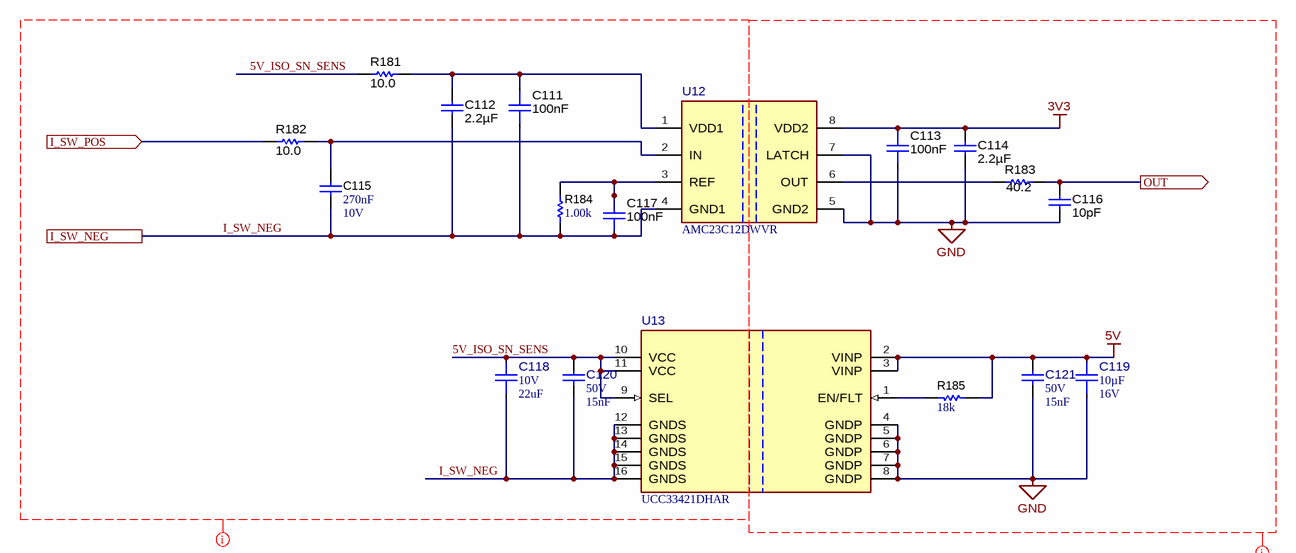
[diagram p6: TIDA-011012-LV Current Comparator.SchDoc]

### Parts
C111  Cap_F: 100nF  [FP-CL10B104KA8VPJC_0603-MFG]  (hidden comment: CL10B104KA8VPJC)
C112  Cap_F: 2.2µF  [0603]  (hidden comment: CC0603KRX7R7BB225)
C113  Cap_F: 100nF  [FP-CL10B104KA8VPJC_0603-MFG]  (hidden comment: CL10B104KA8VPJC)
C114  Cap_F: 2.2µF  [0603]  (hidden comment: CC0603KRX7R7BB225)
C115  Cap_F: 270nF  VDC_V: 10V  [0603]  (hidden comment: C0603C274K8RACTU)
C116  Cap_F: 10pF  [0603]  (hidden comment: 0603ZC100KAT2A)
C117  Cap_F: 100nF  [FP-CL10B104KA8VPJC_0603-MFG]  (hidden comment: CL10B104KA8VPJC)
C118  VDC_V: 10V  ValueDisplayed: 22uF  [FP-GRT21BD71A226ME13L_0805-MFG]  (hidden comment: GRT21BD71A226ME13L)
C119  Cap_F: 10µF  VDC_V: 16V  [FP-MA0805XR106K160_0805-IPC_C]  (hidden comment: MA0805XR106K160)
C120  VDC_V: 50V  Cap_F: 15nF  [FP-C0603C153K5RACTU_0603-IPC_A]  (hidden comment: C0603C153K5RACTU)
C121  VDC_V: 50V  Cap_F: 15nF  [FP-C0603C153K5RACTU_0603-IPC_A]  (hidden comment: C0603C153K5RACTU)
R181  ValueDisplayed: 10.0  [0603]  (hidden comment: TNPW060310R0BEEA)
R182  ValueDisplayed: 10.0  [0603]  (hidden comment: TNPW060310R0BEEA)
R183  ValueDisplayed: 40.2  [0603]  (hidden comment: RC0603FR-0740R2L)
R184  ValueDisplayed: 1.00k  [0603]  (hidden comment: ERJ-3EKF1001V)
R185  ValueDisplayed: 18k  [0603]  (hidden comment: RC0603JR-0718KL)
U12  AMC23C12DWVR  [DWV0008A-MFG]
U13  UCC33421DHAR  [DHA0016A-MFG]

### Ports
I_SW_NEG, I_SW_POS (in), OUT (out)

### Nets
3V3: C113.1 C114.1 U12.8(VDD2)
5V: C119.2 C121.1 R185.2 U13.2(VINP) U13.3(VINP)
GND: C113.2 C114.2 C116.2 C119.1 C121.2 U12.5(GND2) U12.7(LATCH) U13.4(GNDP) U13.5(GNDP) U13.6(GNDP) U13.7(GNDP) U13.8(GNDP)
5V_ISO_SN_SENS: C118.2 C120.1 R181.1 U13.9(SEL) U13.10(VCC) U13.11(VCC)
DC_OC_CMP: C116.1 R183.2 ; port OUT
I_SW_NEG: C111.2 C112.2 C115.2 C117.2 C118.1 C120.2 R184.1 U12.4(GND1) U13.12(GNDS) U13.13(GNDS) U13.14(GNDS) U13.15(GNDS) U13.16(GNDS) ; port I_SW_NEG
I_SW_POS: R182.1 ; port I_SW_POS
NetC111_1: C111.1 C112.1 R181.2 U12.1(VDD1)
NetC115_1: C115.1 R182.2 U12.2(IN)
NetC117_1: C117.1 R184.2 U12.3(REF)
NetR183_1: R183.1 U12.6(OUT)
NetR185_1: R185.1 U13.1(EN/FLT)

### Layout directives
net class HVM: 3V3, 5V, GND
net class HV_DC_SN_N: 5V_ISO_SN_SENS, I_SW_NEG

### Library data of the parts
C111 C113 C117 = CMP-0121051-1: as C73 on sheet TIDA-011012-LV DC IV Sensing
C112 C114 = CMP-0079605-1: as C74 on sheet TIDA-011012-LV DC IV Sensing
C115 = CMP-0006915-5: CAP, CERM, 0.27 uF, 10 V, +/- 10%, X7R, 0603; Manufacturer: Kemet; TaMin_C: -55°C; Polarized: N; SizeAreaWB_mm2: 4.68; Value1: Unknown; U/M: EA; Value: 0.27uF; TaMax_C: 125°C; SizeZ_mm: 1; SizeX_mm: 1.6; SizeY_mm: 0.8; SizeArea_mm2: 1.28; AEC Category: Q200
C116 = CMP-0006811-4: as C153-C155 on sheet TIDA-011012-LV Communication
C118 = CMP-0095621-1: as C89 on sheet TIDA-011012-LV DC IV Sensing
C119 = CMP-0121624-1: as C88 on sheet TIDA-011012-LV DC IV Sensing
C120 C121 = CMP-0086419-2: as C90 on sheet TIDA-011012-LV DC IV Sensing
R181 R182 = CMP-0025687-2: as R151 on sheet TIDA-011012-LV DC IV Sensing
R183 = CMP-0023099-5: as R153 on sheet TIDA-011012-LV DC IV Sensing
R184 = CMP-0022680-4: RES, 1.00 k, 1%, 0.1 W, 0603; Manufacturer: Panasonic; Power_W: 100mW; TempCo: 100 ppm/C; Value_Code: 1k00; U/M: EA; Value: 1.00k; EIA_Code: E96; Res_ohm: 1k; SizeX_mm: 1.6; SizeY_mm: 0.8; SizeZ_mm: 1; SizeArea_mm2: 1.28; VDC_V: 75V; AEC Category: Q200; Value2: 0.1W
R185 = CMP-0025892-5: as R165 on sheet TIDA-011012-LV DC IV Sensing
U12 = CMP-0092444-3: Dual, Fast Response, Reinforced Isolated Window Comparator with Adjustable Threshold; Manufacturer: Texas Instruments; AEC Category: Q200; CompType: IC; SizeZ_mm: 2.8mm; Standoff Height: 0.36mm; Number Of Channels: 2
U13 = CMP-0123146-1: as U8 on sheet TIDA-011012-LV DC IV Sensing

## Sheet TIDA-011012-LV Switch Node Hall Current Sensing.SchDoc
size 431 x 279 mm; Date: Not shown in title block; ApprovedBy: Not shown in title block; CheckedBy: Not shown in title block; Author: Not shown in title block; CompanyName: Not shown in title block; Engineer: Not shown in title block; Organization: Not shown in title block; Address1: Not shown in title block; Address2: Not shown in title block; Address3: Not shown in title block; Address4: Not shown in title block; DocumentNumber: 9; Revision: Use project parameter SCH_Rev; SheetNumber: 9; SheetTotal: 10; PageSetup: Record=PageOptions¦CenterHorizontal=True¦CenterVertical=True¦PrintScale=1.00¦XCorrection=1.00¦YCorrection=1.00¦PrintKind=0¦BorderSize=5000000¦LeftOffset=0¦BottomOffset=0¦Orientation=2¦PaperLength=1000¦PaperWidth=1000¦Scale=100¦PaperSource=15¦PrintQuality=600¦MediaType=1¦DitherType=10¦PaperKind=Letter¦PrintScaleMode=1
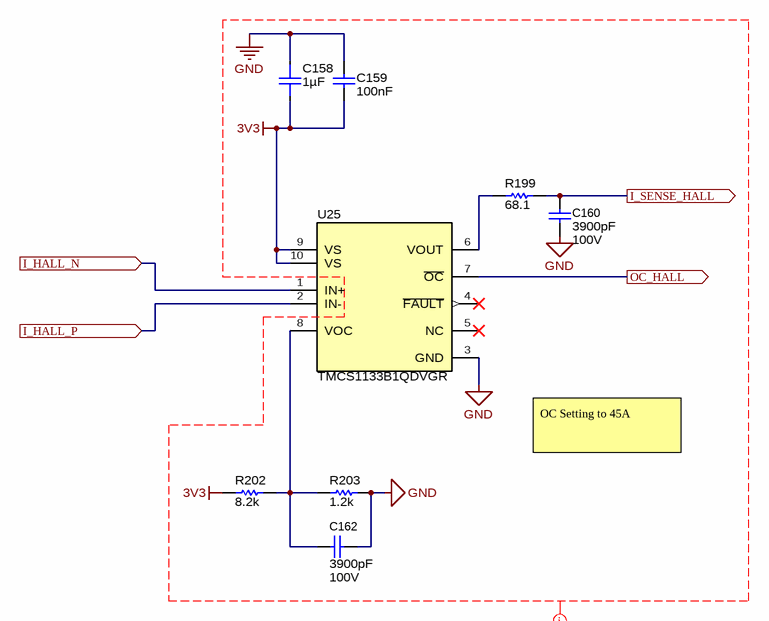
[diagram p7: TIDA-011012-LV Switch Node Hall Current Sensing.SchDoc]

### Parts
C158  Cap_F: 1µF  [FP-CL10B105KA8VPJC_0603-MFG]  (hidden comment: CL10B105KA8VPJC)
C159  Cap_F: 100nF  [0603]  (hidden comment: 06033C104KAT2A)
C160  ValueDisplayed: 3900pF  VDC_V: 100V  [0603]  (hidden comment: C1608C0G2A392J080AE)
C162  ValueDisplayed: 3900pF  VDC_V: 100V  [0603]  (hidden comment: C1608C0G2A392J080AE)
R199  ValueDisplayed: 68.1  [0603]  (hidden comment: CRCW060368R1FKEA)
R202  ValueDisplayed: 8.2k  [0603]  (hidden comment: RC0603JR-078K2L)
R203  ValueDisplayed: 1.2k  [0603]  (hidden comment: RC0603JR-071K2L)
U25  TMCS1133B1QDVGR  [DVG0010A-MFG]

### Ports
I_HALL_N (in), I_HALL_P (in), I_SENSE_HALL (out), OC_HALL (out)

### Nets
3V3: C158.2 C159.1 R202.1 U25.9(VS) U25.10(VS)
GND: C158.1 C159.2 C160.2 C162.2 R203.2 U25.3(GND)
DC_OC: U25.7(~{OC}) ; port OC_HALL
I_HALL: C160.1 R199.2 ; port I_SENSE_HALL
I_HALL_N: U25.1(IN+) ; port I_HALL_N
I_HALL_P: U25.2(IN-) ; port I_HALL_P
NetC162_1: C162.1 R202.2 R203.1 U25.8(VOC)
NetR199_1: R199.1 U25.6(VOUT)

Not connected (* = marked no-connect by the designer): U25 4(~{FAULT})* 5(NC)*

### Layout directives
net class HVM: 3V3, GND

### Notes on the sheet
- OC Setting to 45A

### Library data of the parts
C158 = CMP-0121052-1: Cap Ceramic 1uF 25V X7R ±10% Pad SMD 0603 +125°C T/R; Manufacturer: Samsung; AEC Grade: Grade 1; AEC Qualified: Yes; SizeZ_mm: 0.9mm; TempCo: 15%; Value: 1µF
C159 = CMP-0006753-4: CAP, CERM, 0.1 uF, 25 V, +/- 10%, X7R, 0603; Manufacturer: AVX; TaMin_C: -55°C; ESR_ohm: 0.05; Polarized: N; SizeAreaWB_mm2: 4.68; Value1: 0.05 ohm; U/M: EA; Value: 0.1uF; TaMax_C: 125°C; SizeZ_mm: 1; SizeX_mm: 1.6; SizeY_mm: 0.8; Value2: 25V; SizeArea_mm2: 1.28; AEC Category: Q200
C160 C162 = CMP-0860987-1: CAP, CERM, 3900 pF, 100 V,+/- 5%, C0G/NP0, 0603; Manufacturer: TDK; SizeArea_mm2: 1.28; SizeY_mm: 0.8; AEC Qualified: N; Cap_F: 3.9nF; Value: 3900pF; U/M: EA; AEC Category: Q200; SizeZ_mm: 1; TaMin_C: -55°C; TaMax_C: 125°C; SizeAreaWB_mm2: 4.68; SizeX_mm: 1.6
R199 = CMP-0022553-4: RES, 68.1, 1%, 0.1 W, AEC-Q200 Grade 0, 0603; Manufacturer: Vishay-Dale; Value: 68.1; Value_Code: 68R1; Power_W: 100mW; Value2: 0.1W; VDC_V: 75V; TempCo: 100 ppm/C; SizeArea_mm2: 1.28; SizeX_mm: 1.6; SizeY_mm: 0.8; SizeZ_mm: 1; EIA_Code: E96; AEC Category: Q200; AEC Qualified: Y; AEC Grade: 0
R202 = CMP-0025942-5: RES, 8.2 k, 5%, 0.1 W, 0603; Manufacturer: Yageo; Power_W: 100mW; TempCo: 100 ppm/C; Value_Code: 8k20; Value: 8.2k; EIA_Code: E24; SizeX_mm: 1.6; SizeY_mm: 0.8; SizeZ_mm: 1; Value2: 0.1W; SizeArea_mm2: 1.28; AEC Qualified: N; VDC_V: 75V; AEC Category: Q200; SizeAreaWB_mm2: 4.68
R203 = CMP-0025894-5: RES, 1.2 k, 5%, 0.1 W, 0603; Manufacturer: Yageo; Power_W: 100mW; TempCo: 100 ppm/C; Value_Code: 1k20; Value: 1.2k; EIA_Code: E24; SizeX_mm: 1.6; SizeY_mm: 0.8; SizeZ_mm: 1; Value2: 0.1W; SizeArea_mm2: 1.28; AEC Qualified: N; VDC_V: 75V; AEC Category: Q200; SizeAreaWB_mm2: 4.68
U25 = CMP-0097984-1: Manufacturer: Texas Instruments; Standoff Height: 0.1mm; SizeZ_mm: 2.65mm

## Sheet TIDA-011012-LV  Auxiliary Power.SchDoc
size 431 x 279 mm; Date: Not shown in title block; ApprovedBy: Not shown in title block; CheckedBy: Not shown in title block; Author: Not shown in title block; CompanyName: Not shown in title block; Engineer: Not shown in title block; Organization: Not shown in title block; Address1: Not shown in title block; Address2: Not shown in title block; Address3: Not shown in title block; Address4: Not shown in title block; DocumentNumber: 3; Revision: Use project parameter SCH_Rev; SheetNumber: 3; SheetTotal: 10; PageSetup: Record=PageOptions¦CenterHorizontal=True¦CenterVertical=True¦PrintScale=1.00¦XCorrection=1.00¦YCorrection=1.00¦PrintKind=0¦BorderSize=5000000¦LeftOffset=0¦BottomOffset=0¦Orientation=2¦PaperLength=1000¦PaperWidth=1000¦Scale=100¦PaperSource=15¦PrintQuality=600¦MediaType=1¦DitherType=10¦PaperKind=Letter¦PrintScaleMode=1
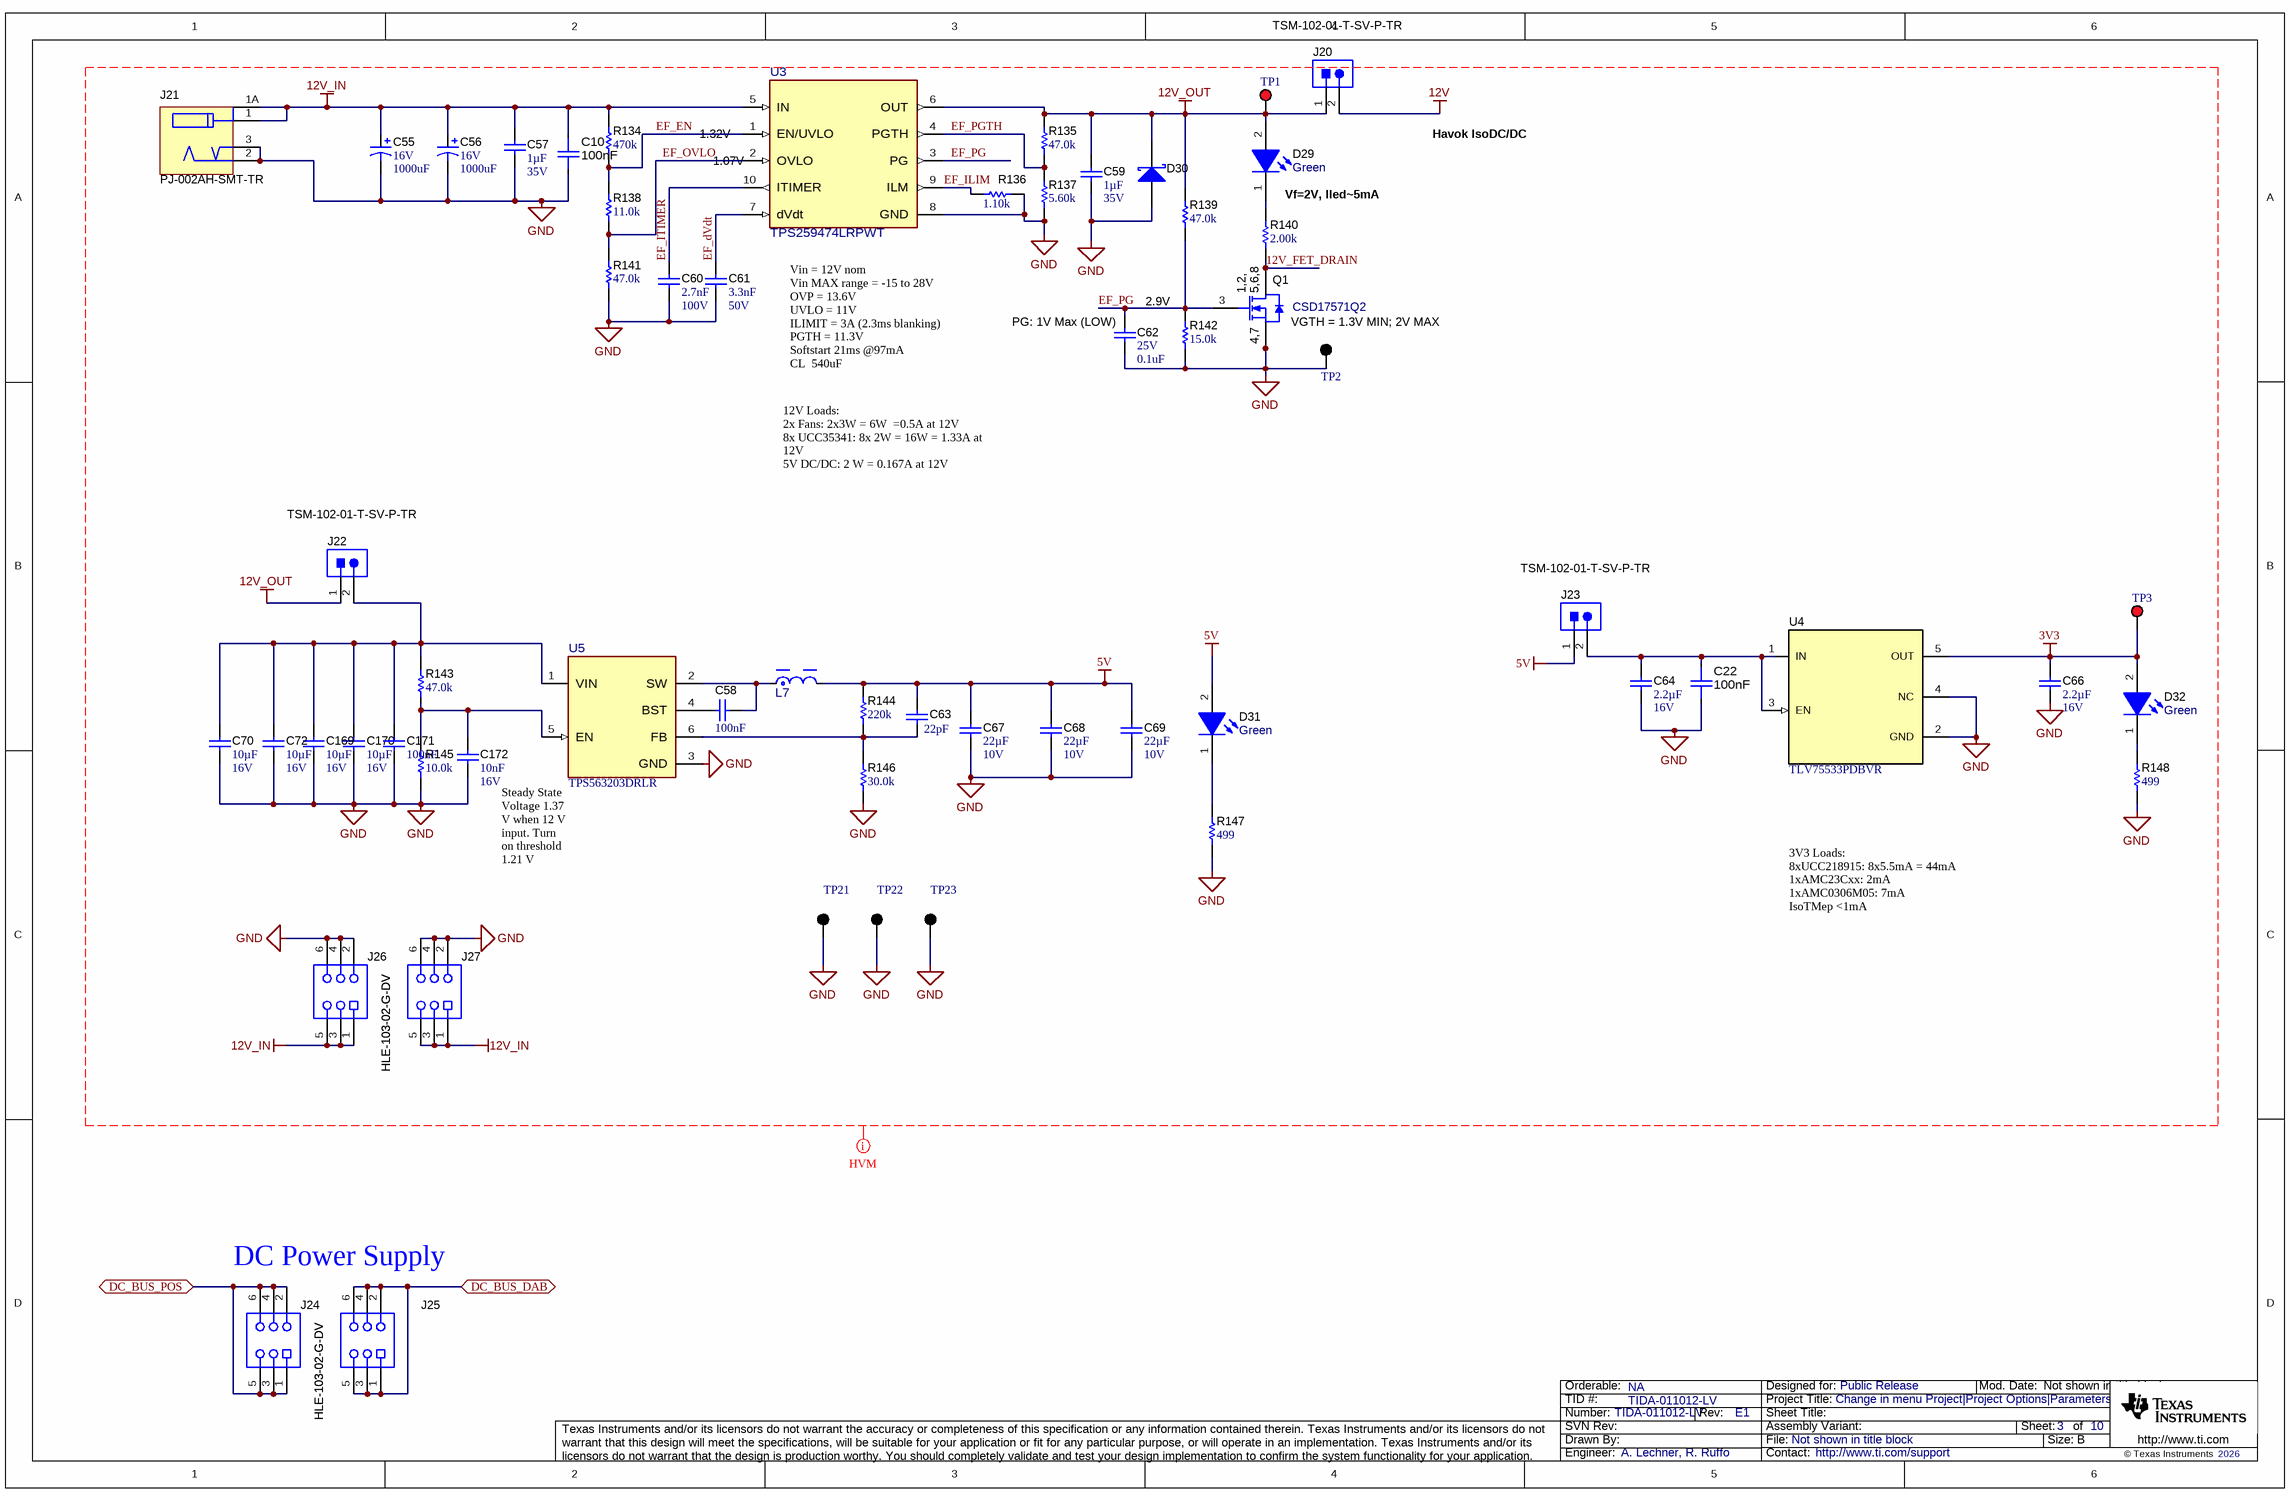
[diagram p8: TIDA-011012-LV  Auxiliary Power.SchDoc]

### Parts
C10  Cap_F: 100nF  [FP-CL10B104KA8VPJC_0603-MFG]  (hidden comment: CL10B104KA8VPJC)
C22  Cap_F: 100nF  [FP-CL10B104KA8VPJC_0603-MFG]  (hidden comment: CL10B104KA8VPJC)
C55  VDC_V: 16V  ValueDisplayed: 1000uF  [CAPPR5-10x16]  (hidden comment: 16ZLJ1000MCE10X16)
C56  VDC_V: 16V  ValueDisplayed: 1000uF  [CAPPR5-10x16]  (hidden comment: 16ZLJ1000MCE10X16)
C57  Cap_F: 1µF  VDC_V: 35V  [0603]  (hidden comment: C1608X7R1V105K080AC)
C58  Cap_F: 100nF  [0603]  (hidden comment: 06033C104JAT2A)
C59  Cap_F: 1µF  VDC_V: 35V  [0603]  (hidden comment: C1608X7R1V105K080AC)
C60  Cap_F: 2.7nF  VDC_V: 100V  [0603]  (hidden comment: GRM188R72A272KA01D)
C61  Cap_F: 3.3nF  VDC_V: 50V  [0603]  (hidden comment: C0603X332K5RACTU)
C62  VDC_V: 25V  ValueDisplayed: 0.1uF  [0402L]  (hidden comment: GRM155R71E104KE14D)
C63  ValueDisplayed: 22pF  [0603]  (hidden comment: GRM1885C2A220JA01D)
C64  Cap_F: 2.2µF  VDC_V: 16V  [0603]  (hidden comment: EMK107BB7225KA-T)
C66  Cap_F: 2.2µF  VDC_V: 16V  [0603]  (hidden comment: EMK107BB7225KA-T)
C67  Cap_F: 22µF  VDC_V: 10V  [0805_HV]  (hidden comment: GRM21BZ71A226ME15L)
C68  Cap_F: 22µF  VDC_V: 10V  [0805_HV]  (hidden comment: GRM21BZ71A226ME15L)
C69  Cap_F: 22µF  VDC_V: 10V  [0805_HV]  (hidden comment: GRM21BZ71A226ME15L)
C70  Cap_F: 10µF  VDC_V: 16V  [0805_HV]  (hidden comment: EMK212BB7106KG-T)
C72  Cap_F: 10µF  VDC_V: 16V  [0805_HV]  (hidden comment: EMK212BB7106KG-T)
C169  Cap_F: 10µF  VDC_V: 16V  [0805_HV]  (hidden comment: EMK212BB7106KG-T)
C170  Cap_F: 10µF  VDC_V: 16V  [0805_HV]  (hidden comment: EMK212BB7106KG-T)
C171  Cap_F: 100nF  [0603]  (hidden comment: 06033C104JAT2A)
C172  Cap_F: 10nF  VDC_V: 16V  [0603]  (hidden comment: C0603C103K4RACTU)
D29  value Green  [WL-SMCW_GREEN]  (hidden comment: 150060VS75000)
D30  B330A-13-F  [SMA]  (value not drawn)
D31  value Green  [WL-SMCW_GREEN]  (hidden comment: 150060VS75000)
D32  value Green  [WL-SMCW_GREEN]  (hidden comment: 150060VS75000)
J20  TSM-102-01-T-SV-P-TR  [Samtec_TSM-102-01-T-SV-P-TR]
J21  PJ-002AH-SMT-TR  [CUI_PJ-002AH-SMT]
J22  TSM-102-01-T-SV-P-TR  [Samtec_TSM-102-01-T-SV-P-TR]
J23  TSM-102-01-T-SV-P-TR  [Samtec_TSM-102-01-T-SV-P-TR]
J24  HLE-103-02-G-DV  [Samtec_HLE-103-02-x-DV]
J25  HLE-103-02-G-DV  [Samtec_HLE-103-02-x-DV]
J26  HLE-103-02-G-DV  [Samtec_HLE-103-02-x-DV]
J27  HLE-103-02-G-DV  [Samtec_HLE-103-02-x-DV]
L7  74439324047  [FP-74439324047_SMD2-MFG]  (value not drawn)
Q1  CSD17571Q2  [DQK0006C]
R134  ValueDisplayed: 470k  [0603]  (hidden comment: RC0603FR-07470KL)
R135  ValueDisplayed: 47.0k  [0603]  (hidden comment: RC0603FR-0747KL)
R136  ValueDisplayed: 1.10k  [0603]  (hidden comment: RC0603FR-071K1L)
R137  ValueDisplayed: 5.60k  [0603]  (hidden comment: RC0603FR-075K6L)
R138  ValueDisplayed: 11.0k  [0603]  (hidden comment: RC0603FR-0711KL)
R139  ValueDisplayed: 47.0k  [0603]  (hidden comment: RC0603FR-0747KL)
R140  ValueDisplayed: 2.00k  [0603]  (hidden comment: RC0603FR-072KL)
R141  ValueDisplayed: 47.0k  [0603]  (hidden comment: RC0603FR-0747KL)
R142  ValueDisplayed: 15.0k  [0603]  (hidden comment: RC0603FR-0715KL)
R143  ValueDisplayed: 47.0k  [0603]  (hidden comment: RC0603FR-0747KL)
R144  ValueDisplayed: 220k  [0603]  (hidden comment: RC0603FR-07220KL)
R145  ValueDisplayed: 10.0k  [0603]  (hidden comment: RG1608P-103-B-T5)
R146  ValueDisplayed: 30.0k  [0603]  (hidden comment: RC0603FR-0730KL)
R147  ValueDisplayed: 499  [0603]  (hidden comment: CRCW0603499RFKEAC)
R148  ValueDisplayed: 499  [0603]  (hidden comment: CRCW0603499RFKEAC)
TP1  5010  [Keystone5010]  (value not drawn)
TP2  5011  [Keystone5011]  (value not drawn)
TP3  5010  [Keystone5010]  (value not drawn)
TP21  5011  [Keystone5011]  (value not drawn)
TP22  5011  [Keystone5011]  (value not drawn)
TP23  5011  [Keystone5011]  (value not drawn)
U3  TPS259474LRPWT  [RPW0010A-MFG]
U4  TLV75533PDBVR  [DBV0005A_N]
U5  TPS563203DRLR  [DRL0006A-MFG]

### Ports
DC_BUS_DAB (bidir), DC_BUS_POS (bidir)

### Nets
3V3: C66.1 D32.2(A) TP3.1 U4.5(OUT)
5V: C63.1 C67.1 C68.1 C69.1 D31.2(A) J23.1 L7.2 R144.2
12V: J20.2
12V_IN: C10.1 C55.1(+) C56.1(+) C57.1 J21.1 J21.1A J26.1 J26.3 J26.5 J27.1 J27.3 J27.5 R134.2 U3.5(IN)
12V_OUT: C59.1 D29.2(A) D30.1(K) J20.1 J22.1 R135.2 R139.2 TP1.1 U3.6(OUT)
GND: C10.2 C22.2 C55.2(-) C56.2(-) C57.2 C59.2 C60.2 C61.2 C62.2 C64.2 C66.2 C67.2 C68.2 C69.2 C70.2 C72.2 C169.2 C170.2 C171.1 C172.2 D30.2(A) J21.2 J21.3 J26.2 J26.4 J26.6 J27.2 J27.4 J27.6 Q1.4(S) Q1.7(S) R136.1 R137.1 R141.1 R142.1 R145.2 R146.1 R147.1 R148.1 TP2.1 TP21.1 TP22.1 TP23.1 U3.8(GND) U4.2(GND) U4.4(NC) U5.3(GND)
12V_FET_DRAIN: Q1.1(D) Q1.2(D) Q1.5(D) Q1.6(D) Q1.8(D) R140.1
DC_DAB: J25.1 J25.2 J25.3 J25.4 J25.5 J25.6 ; port DC_BUS_DAB
DC_POS: J24.1 J24.2 J24.3 J24.4 J24.5 J24.6 ; port DC_BUS_POS
EF_dVdt: C61.1 U3.7(dVdt)
EF_EN: R134.1 R138.2 U3.1(EN/UVLO)
EF_ILIM: R136.2 U3.9(ILM)
EF_ITIMER: C60.1 U3.10(ITIMER)
EF_OVLO: R138.1 R141.2 U3.2(OVLO)
EF_PG: C62.1 Q1.3(G) R139.1 R142.2 U3.3(PG)
EF_PGTH: R135.1 R137.2 U3.4(PGTH)
NetC22_1: C22.1 C64.1 J23.2 U4.1(IN) U4.3(EN)
NetC58_1: C58.1 U5.4(BST)
NetC58_2: C58.2 L7.1 U5.2(SW)
NetC63_2: C63.2 R144.1 R146.2 U5.6(FB)
NetC70_1: C70.1 C72.1 C169.1 C170.1 C171.2 J22.2 R143.2 U5.1(VIN)
NetC172_1: C172.1 R143.1 R145.1 U5.5(EN)
NetD29_1: D29.1(K) R140.2
NetD31_1: D31.1(K) R147.2
NetD32_1: D32.1(K) R148.2

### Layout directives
net class HVM: 3V3, 5V, 12V, 12V_FET_DRAIN, 12V_IN, 12V_OUT, EF_dVdt, EF_EN, EF_ILIM, EF_ITIMER, EF_OVLO, EF_PG, EF_PGTH, GND

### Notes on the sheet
- (near U3) 1.32V
- (near U3) 1.07V
- Havok IsoDC/DC
- Vf=2V, Iled~5mA
- 2.9V
- Vin = 12V nom
  Vin MAX range = -15 to 28V
  OVP = 13.6V
  UVLO = 11V
  ILIMIT = 3A (2.3ms blanking)
  PGTH = 11.3V
  Softstart 21ms @97mA
  CL  540uF
- (near C62) PG: 1V Max (LOW)
- VGTH = 1.3V MIN; 2V MAX
- 12V Loads:
  2x Fans: 2x3W = 6W  =0.5A at 12V
  8x UCC35341: 8x 2W = 16W = 1.33A at 12V
  5V DC/DC: 2 W = 0.167A at 12V
- (near U5) Steady State Voltage 1.37 V when 12 V input. Turn on threshold 1.21 V
- 3V3 Loads:
  8xUCC218915: 8x5.5mA = 44mA
  1xAMC23Cxx: 2mA
  1xAMC0306M05: 7mA
  IsoTMep <1mA
- DC Power Supply

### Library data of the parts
C10 C22 = CMP-0121051-1: as C73 on sheet TIDA-011012-LV DC IV Sensing
C55 C56 = CMP-0010289-1: CAP, AL, 1000 uF, 16 V, +/- 20%, TH; Manufacturer: Rubycon; TaMin_C: -40°C; Polarized: Y; SizeAreaWB_mm2: 144; Value1: Unknown; U/M: EA; Value: 1000uF; TaMax_C: 105°C; SizeZ_mm: 17.5; SizeX_mm: 10; Cap_Case: 10x16; SizeArea_mm2: 100; CompType: Capacitor; AEC Qualified: N; Cap_F: 1mF; AEC Category: Q200
C57 C59 = CMP-0007052-4: CAP, CERM, 1 uF, 35 V, +/- 10%, X7R, 0603; Manufacturer: TDK; TaMin_C: -55°C; Polarized: N; SizeAreaWB_mm2: 4.68; Value1: Unknown; U/M: EA; Value: 1uF; TaMax_C: 125°C; SizeZ_mm: 1; SizeX_mm: 1.6; SizeY_mm: 0.8; SizeArea_mm2: 1.28; AEC Category: Q200
C58 C171 = CMP-0006752-5: CAP, CERM, 0.1 uF, 25 V, +/- 5%, X7R, 0603; Manufacturer: AVX; TaMin_C: -55°C; ESR_ohm: 0.05; Polarized: N; SizeAreaWB_mm2: 4.68; Value1: 0.05 ohm; U/M: EA; Value: 0.1uF; TaMax_C: 125°C; SizeZ_mm: 1; SizeX_mm: 1.6; SizeY_mm: 0.8; Value2: 25V; SizeArea_mm2: 1.28; AEC Category: Q200
C60 = CMP-0007477-4: CAP, CERM, 2700 pF, 100 V, +/- 10%, X7R, 0603; Manufacturer: MuRata; TaMin_C: -55°C; Polarized: N; SizeAreaWB_mm2: 4.68; Value1: Unknown; U/M: EA; Value: 2700pF; TaMax_C: 125°C; SizeZ_mm: 1; SizeX_mm: 1.6; SizeY_mm: 0.8; SizeArea_mm2: 1.28; AEC Category: Q200
C61 = CMP-0006985-4: CAP, CERM, 3300 pF, 50 V, +/- 10%, X7R, 0603; Manufacturer: Kemet; TaMin_C: -55°C; Polarized: N; SizeAreaWB_mm2: 4.68; Value1: Unknown; U/M: EA; Value: 3300pF; TaMax_C: 125°C; SizeZ_mm: 1; SizeX_mm: 1.6; SizeY_mm: 0.8; SizeArea_mm2: 1.28; AEC Category: Q200
C62 = CMP-0006659-2: CAP, CERM, 0.1 uF, 25 V, +/- 10%, X7R, 0402; Manufacturer: MuRata; TaMin_C: -55°C; Polarized: N; SizeAreaWB_mm2: 3; Value1: Unknown; U/M: EA; Value: 0.1uF; TaMax_C: 125°C; SizeZ_mm: 0.6; SizeX_mm: 1; SizeY_mm: 0.5; Cap_Case: 0402; Cap_F: 100nF; AEC Category: Q200
C63 = CMP-0007255-4: CAP, CERM, 22 pF, 100 V, +/- 5%, C0G/NP0, 0603; Manufacturer: MuRata; TaMin_C: -55°C; Polarized: N; SizeAreaWB_mm2: 4.68; Value1: Unknown; U/M: EA; Value: 22pF; TaMax_C: 125°C; SizeZ_mm: 1; SizeX_mm: 1.6; SizeY_mm: 0.8; Value2: 100V; SizeArea_mm2: 1.28; AEC Category: Q200
C64 C66 = CMP-0007121-4: CAP, CERM, 2.2 uF, 16 V, +/- 10%, X7R, 0603; Manufacturer: Taiyo Yuden; TaMin_C: -55°C; Polarized: N; SizeAreaWB_mm2: 4.68; Value1: Unknown; U/M: EA; Value: 2.2uF; TaMax_C: 125°C; SizeZ_mm: 1; SizeX_mm: 1.6; SizeY_mm: 0.8; SizeArea_mm2: 1.28; AEC Category: Q200
C67-C69 = CMP-0008377-2: CAP, CERM, 22 uF, 10 V, +/- 20%, X7R, 0805; Manufacturer: MuRata; SizeY_mm: 1.25; Cap_Case: 0805; SizeArea_mm2: 2.5; AEC Qualified: N; AEC Category: Q200; ValueDisplayed: 22uF; TaMin_C: -55°C; SizeAreaWB_mm2: 6.75; Value1: Unknown; U/M: EA; Value: 22uF; TaMax_C: 125°C; SizeZ_mm: 1.45; SizeX_mm: 2
C70 C72 C169 C170 = CMP-0085283-1: CAP, CERM, 10 µF, 16 V,+/- 10%, X7R, 0805; Manufacturer: Taiyo Yuden; TaMin_C: -55°C; AEC Qualified: N; U/M: EA; TaMax_C: 125°C; SizeAreaWB_mm2: 6.75; SizeZ_mm: 1.45; Value: 10uF; SizeY_mm: 1.25; SizeArea_mm2: 2.5; AEC Category: Q200; SizeX_mm: 2; Cap_Case: 0805
C172 = CMP-0006853-4: CAP, CERM, 0.01 uF, 16 V, +/- 10%, X7R, 0603; Manufacturer: Kemet; TaMin_C: -55°C; Polarized: N; SizeAreaWB_mm2: 4.68; Value1: Unknown; U/M: EA; Value: 0.01uF; TaMax_C: 125°C; SizeZ_mm: 1; SizeX_mm: 1.6; SizeY_mm: 0.8; SizeArea_mm2: 1.28; AEC Category: Q200
D29 D31 D32 = CMP-0002894-2: as D26 on sheet TIDA-011012-LV Communication
D30 = CMP-0028350-2: Diode, Schottky, 30 V, 3 A, SMA; Manufacturer: Diodes Inc.; Io_A: 3A; SizeZ_mm: 2.87; SizeAreaWB_mm2: 37.3428; Value: 30V; TJmax_C: 125°C; Green_Lifecycle: Active; SizeY_mm: 2.92; Vf_V: 500mV; Green_REACh: Passed; SizeArea_mm2: 16.3228; AEC Category: Q101; Value2: 0.5V; SizeX_mm: 5.59; RJC_CperW: 25
J20 J22 J23 = CMP-0075491-1: Header, 100mil, 2x1, Tin, SMD; Manufacturer: Samtec; Pitch_mm: 2.54; Gender: Male; Cert_CSA: Y; Current_A: 5.4A; Voltage_V: 475V; CT: False; Shrouded: N; Row_Count: 1; CNHeader: True
J21 = CMP-0075012-1: Power Jack, SMT; Manufacturer: CUI Inc.; Green_Lifecycle: Not Set; Green_REACh: Incomplete; CNHeader: False
J24-J27 = CMP-0082272-1: Receptacle, 2.54mm, 3x2, Gold, SMT; Manufacturer: Samtec; Pitch_mm: 2.54; Gender: Female; Cert_UL: Y; Voltage_V: 400V; Current_A: 4.1A; Row_Count: 2; CompType: Socket Strip
L7 = CMP-0128921-1: 4.7 µH Shielded Molded Inductor 5.3 A 36.96mOhm Max Nonstandard; Manufacturer: Wurth; AEC Grade: Grade 1; AEC Qualified: Yes; DCR_ohm: 36.96m; Ind_H: 4.7µH; Irms: 5.3A; Isat: 2.8A; Material: Iron; SizeZ_mm: 3.2mm; Value: 4.7uH; Self Resonant Frequency: 28MHz; Shrouded: true; TaMax_C: +85°C; TaMin_C: -40°C; Test Frequency: 100kHz; Tolerance_%: 20%
Q1 = CMP-0000585-1: MOSFET, N-CH, 30 V, 22 A, DQK0006C (WSON-6); Alternate Manufacturer: None; Manufacturer: Texas Instruments; SizeZ_mm: 0.8; ChType: N; Value2: 2.4 nC; Value1: 0.02; VdsMax_V: 30V; SizeX_mm: 2; Vgs_V: 20V; Value: 30V; Rdson45_ohm: 0.029; SizeArea_mm2: 4; AEC Category: Q101; IdsMax_A: 22A; SizeAreaWB_mm2: 9; U/M: EA; QgTyp_nC: 2.4
R134 = CMP-0023128-4: RES, 470 k, 1%, 0.1 W, 0603; Manufacturer: Yageo; Power_W: 100mW; TempCo: 100 ppm/C; Value: 470k; SizeX_mm: 1.6; SizeY_mm: 0.8; SizeZ_mm: 1; Value2: 0.1W; SizeArea_mm2: 1.28; AEC Qualified: N; VDC_V: 75V; AEC Category: Q200; SizeAreaWB_mm2: 4.68
R135 R139 R141 R143 = CMP-0023133-5: RES, 47.0 k, 1%, 0.1 W, 0603; Manufacturer: Yageo; Power_W: 100mW; TempCo: 100 ppm/C; Value_Code: 47k0; Value: 47.0k; Res_ohm: 47k; SizeX_mm: 1.6; SizeY_mm: 0.8; SizeZ_mm: 1; Value2: 0.1W; SizeArea_mm2: 1.28; AEC Qualified: N; VDC_V: 75V; AEC Category: Q200; SizeAreaWB_mm2: 4.68
R136 = CMP-0022870-5: RES, 1.10 k, 1%, 0.1 W, 0603; Manufacturer: Yageo; Power_W: 100mW; TempCo: 100 ppm/C; Value_Code: 1k10; Value: 1.10k; EIA_Code: E96; Res_ohm: 1.1k; SizeX_mm: 1.6; SizeY_mm: 0.8; SizeZ_mm: 1; Value2: 0.1W; SizeArea_mm2: 1.28; AEC Qualified: N; VDC_V: 75V; AEC Category: Q200; SizeAreaWB_mm2: 4.68
R137 = CMP-0023203-5: RES, 5.60 k, 1%, 0.1 W, 0603; Manufacturer: Yageo; Power_W: 100mW; TempCo: 100 ppm/C; Value_Code: 5k60; Value: 5.60k; Res_ohm: 5.6k; SizeX_mm: 1.6; SizeY_mm: 0.8; SizeZ_mm: 1; Value2: 0.1W; SizeArea_mm2: 1.28; AEC Qualified: N; VDC_V: 75V; AEC Category: Q200; SizeAreaWB_mm2: 4.68
R138 = CMP-0022763-5: RES, 11.0 k, 1%, 0.1 W, 0603; Manufacturer: Yageo; Power_W: 100mW; TempCo: 100 ppm/C; Value_Code: 11k0; Value: 11.0k; EIA_Code: E96; Res_ohm: 11k; SizeX_mm: 1.6; SizeY_mm: 0.8; SizeZ_mm: 1; Value2: 0.1W; SizeArea_mm2: 1.28; AEC Qualified: N; VDC_V: 75V; AEC Category: Q200; SizeAreaWB_mm2: 4.68
R140 = CMP-0023000-5: RES, 2.00 k, 1%, 0.1 W, 0603; Manufacturer: Yageo; Power_W: 100mW; TempCo: 100 ppm/C; Value_Code: 2k00; Value: 2.00k; EIA_Code: E96; Res_ohm: 2k; SizeX_mm: 1.6; SizeY_mm: 0.8; SizeZ_mm: 1; Value2: 0.1W; SizeArea_mm2: 1.28; AEC Qualified: N; VDC_V: 75V; AEC Category: Q200; SizeAreaWB_mm2: 4.68
R142 = CMP-0022816-5: RES, 15.0 k, 1%, 0.1 W, 0603; Manufacturer: Yageo; Power_W: 100mW; TempCo: 100 ppm/C; Value_Code: 15k0; Value: 15.0k; EIA_Code: E96; Res_ohm: 15k; SizeX_mm: 1.6; SizeY_mm: 0.8; SizeZ_mm: 1; Value2: 0.1W; SizeArea_mm2: 1.28; AEC Qualified: N; VDC_V: 75V; AEC Category: Q200; SizeAreaWB_mm2: 4.68
R144 = CMP-0022917-4: RES, 220 k, 1%, 0.1 W, 0603; Manufacturer: Yageo; Power_W: 100mW; TempCo: 100 ppm/C; Value: 220k; SizeX_mm: 1.6; SizeY_mm: 0.8; SizeZ_mm: 1; Value2: 0.1W; SizeArea_mm2: 1.28; AEC Qualified: N; VDC_V: 75V; AEC Category: Q200; SizeAreaWB_mm2: 4.68
R145 = CMP-0023404-3: RES, 10.0 k, 0.1%, 0.1 W, 0603; Manufacturer: Susumu Co Ltd; Power_W: 100mW; TempCo: 25 ppm/C; Value_Code: 10k0; U/M: EA; Value: 10.0k; EIA_Code: E192; Res_ohm: 10k; SizeX_mm: 1.6; SizeY_mm: 0.8; SizeZ_mm: 1; Value2: 0.1W; SizeArea_mm2: 1.28; VDC_V: 75V; AEC Category: Q200
R146 = CMP-0023020-5: RES, 30.0 k, 1%, 0.1 W, 0603; Manufacturer: Yageo; Power_W: 100mW; TempCo: 100 ppm/C; Value_Code: 30k0; Value: 30.0k; Res_ohm: 30k; SizeX_mm: 1.6; SizeY_mm: 0.8; SizeZ_mm: 1; Value2: 0.1W; SizeArea_mm2: 1.28; AEC Qualified: N; VDC_V: 75V; AEC Category: Q200; SizeAreaWB_mm2: 4.68
R147 R148 = CMP-0082532-1: as R48 on sheet TIDA-011012-LV Communication
TP1 TP3 = CMP-0055147-2: Test Point, Multipurpose, Red, TH; Manufacturer: Keystone Electronics; CT: TRUE; ContactFinish: Silver; Green_Lifecycle: Active; CNHeader: FALSE; Green_REACh: Passed
TP2 TP21-TP23 = CMP-0055148-2: Test Point, Multipurpose, Black, TH; Manufacturer: Keystone Electronics; CNHeader: FALSE; ContactFinish: Silver; Green_REACh: Passed; Green_Lifecycle: Active; CT: TRUE
U3 = CMP-0088329-1: 2.7- 23V, 5.5 A, 28 mΩ Reverse Current Blocking eFuse with Input Reverse Polarity Protection; Manufacturer: Texas Instruments; AEC Qualified: No; Nominal Supply Current: 0.5-6A; Threshold Voltage: 1.2/1.1V; Standoff Height: 0mm; Number Of Rails Monitored: 1; SizeZ_mm: 1mm; Min Supply Voltage: 2.7V; Reset Type: Active Low; TJmax_C: +125°C; Output Voltage: 42V
U4 = CMP-0074640-3: 500-mA, Low IQ, Small Size, Low Dropout Regulator, DBV0005A (SOT-23-5); Manufacturer: Texas Instruments; SizeX_mm: 2.8; SizeY_mm: 2.9; CompType: IC; SizeZ_mm: 1.45; SizeArea_mm2: 8.12; SizeAreaWB_mm2: 14.82; AEC Category: Q200; AEC Qualified: N
U5 = CMP-0047826-1: 4.2-V to 17-V Input, 3-A Synchronous Buck Converter in SOT563; Manufacturer: Texas Instruments; SizeZ_mm: 0.6mm; AEC Qualified: No; Max Duty Cycle: 95%; Max Supply Voltage: 17V; Min Supply Voltage: 4.2V; Nominal Supply Current: 110uA; Number Of Outputs: 1; Output Type: AdjustableProgrammable; Output Voltage: 0.6-7V; Standoff Height: 0mm; Switching Frequency: 600kHz; TJmax_C: +125°C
